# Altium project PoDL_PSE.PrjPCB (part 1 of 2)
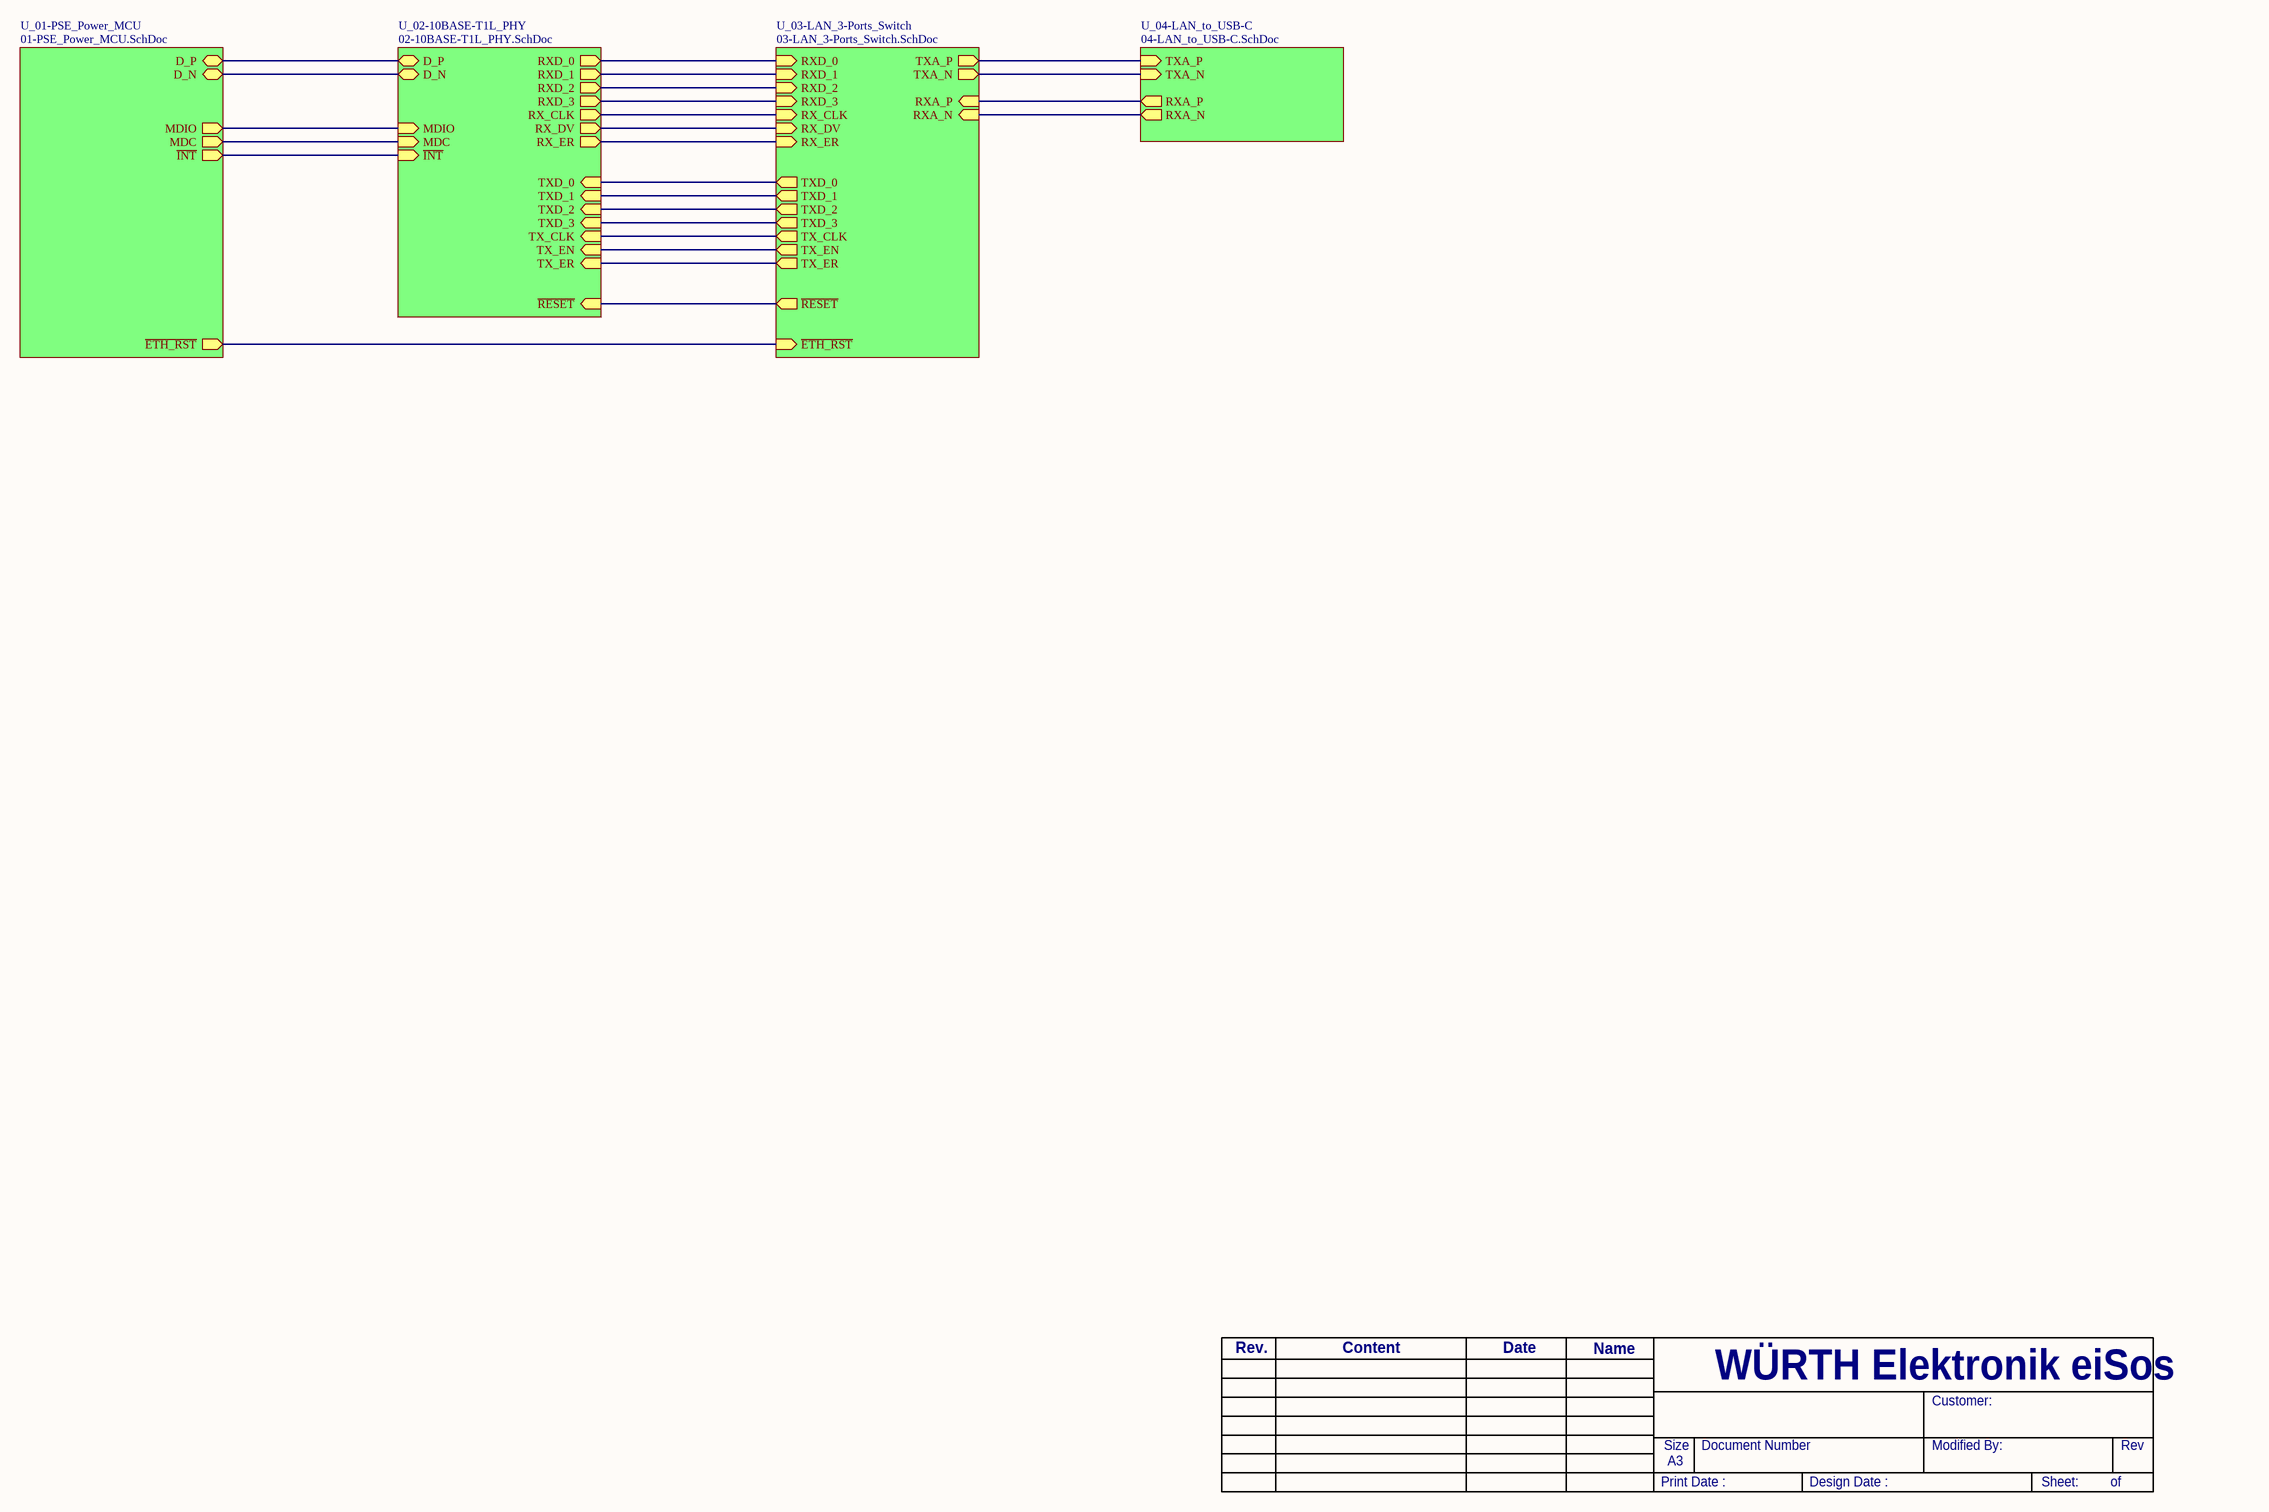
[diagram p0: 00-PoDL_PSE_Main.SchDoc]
5 sheets, 431 parts. Net scope: hierarchical (ports join the sheet entries above them; power ports are global).
Board file: PoDL_PSE_V16.PcbDoc
Sheets:
  00-PoDL_PSE_Main.SchDoc
    U_01-PSE_Power_MCU = 01-PSE_Power_MCU.SchDoc
    U_02-10BASE-T1L_PHY = 02-10BASE-T1L_PHY.SchDoc
    U_03-LAN_3-Ports_Switch = 03-LAN_3-Ports_Switch.SchDoc
    U_04-LAN_to_USB-C = 04-LAN_to_USB-C.SchDoc

## Sheet 00-PoDL_PSE_Main.SchDoc: PSE Main
size A2; Date: Thu 9th Mar, 2023; CompanyName: RGT Supply and Service Ltd.; Engineer: Nattawut; Address1: 285/95 M.3 T.Tonpao Sankampaeng; Address2: Chiangmai 50130 Thailand Tel.+66 89 1645339; Revision: 1.6; SheetNumber: 0; SheetTotal: 4; ContentRev1: Original Document; dateREV1: 09-03-2023; NameRev1: Nattawut; NameRev3: Nattawut; NameRev2: Nattawut; NameRev4: Nattawut; NameRev5: Nattawut; NameRev6: Nattawut; dateREV2: 10-05-2023; dateREV3: 29-10-2023; dateREV4: 13-12-2023; dateREV5: 14-05-2024; dateREV6: 04-07-2024; ContentRev2: Change to AD controller; ContentRev3: Update Power Coupling; ContentRev4: Correct for IC4 unused ports; ContentRev5: Improve for EMC ability; ContentRev6: Add D36, Replace FB7 to R162; Rev1: 1.0; Rev2: 1.1; Rev3: 1.2; Rev4: 1.3; Rev5: 1.4; Rev6: 1.5; Project: PoDL; PageSetup: Record=PageOptions¦CenterHorizontal=True¦CenterVertical=True¦PrintScale=0.73¦XCorrection=1.00¦YCorrection=1.00¦PrintKind=0¦BorderSize=5000000¦LeftOffset=0¦BottomOffset=0¦Orientation=2¦PaperLength=1000¦PaperWidth=1000¦Scale=100¦PaperSource=7¦PrintQuality=-3¦MediaType=1¦DitherType=10¦PrintScaleMode=1¦PaperKind=A3¦PaperIndex=8; dateREV7: 15-09-2024; NameRev7: Nattawut; Rev7: 1.6; ContentRev7: Improve for EMC ability

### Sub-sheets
U_01-PSE_Power_MCU = 01-PSE_Power_MCU.SchDoc: D_P (bidir), D_N (bidir), MDIO (out), ~{ETH_RST} (out), MDC (out), ~{INT} (out)
U_02-10BASE-T1L_PHY = 02-10BASE-T1L_PHY.SchDoc: RXD_0 (out), RXD_1 (out), RXD_2 (out), RXD_3 (out), RX_CLK (out), RX_DV (out), RX_ER (out), TX_ER (in), TX_EN (in), TX_CLK (in), TXD_0 (in), TXD_1 (in), TXD_3 (in), TXD_2 (in), D_P (bidir), D_N (bidir), ~{RESET} (in), MDIO (in), MDC (in), ~{INT} (in)
U_03-LAN_3-Ports_Switch = 03-LAN_3-Ports_Switch.SchDoc: TXA_N (out), TXA_P (out), RXA_N (in), RXA_P (in), ~{RESET} (out), RXD_0 (in), RX_CLK (in), RX_DV (in), RX_ER (in), TX_ER (out), TX_EN (out), TX_CLK (out), TXD_0 (out), TXD_1 (out), RXD_1 (in), RXD_2 (in), RXD_3 (in), TXD_3 (out), TXD_2 (out), ~{ETH_RST} (in)
U_04-LAN_to_USB-C = 04-LAN_to_USB-C.SchDoc: TXA_N (in), TXA_P (in), RXA_N (out), RXA_P (out)

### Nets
D_N: sheet U_01-PSE_Power_MCU/D_N, sheet U_02-10BASE-T1L_PHY/D_N
D_P: sheet U_01-PSE_Power_MCU/D_P, sheet U_02-10BASE-T1L_PHY/D_P
~{ETH_RST}: sheet U_01-PSE_Power_MCU/~{ETH_RST}, sheet U_03-LAN_3-Ports_Switch/~{ETH_RST}
~{INT}: sheet U_01-PSE_Power_MCU/~{INT}, sheet U_02-10BASE-T1L_PHY/~{INT}
MDC: sheet U_01-PSE_Power_MCU/MDC, sheet U_02-10BASE-T1L_PHY/MDC
MDIO: sheet U_01-PSE_Power_MCU/MDIO, sheet U_02-10BASE-T1L_PHY/MDIO
P0_INCLK: sheet U_02-10BASE-T1L_PHY/RX_CLK, sheet U_03-LAN_3-Ports_Switch/RX_CLK
P0_IND0: sheet U_02-10BASE-T1L_PHY/RXD_0, sheet U_03-LAN_3-Ports_Switch/RXD_0
P0_IND1: sheet U_02-10BASE-T1L_PHY/RXD_1, sheet U_03-LAN_3-Ports_Switch/RXD_1
P0_IND2: sheet U_02-10BASE-T1L_PHY/RXD_2, sheet U_03-LAN_3-Ports_Switch/RXD_2
P0_IND3: sheet U_02-10BASE-T1L_PHY/RXD_3, sheet U_03-LAN_3-Ports_Switch/RXD_3
P0_INDV: sheet U_02-10BASE-T1L_PHY/RX_DV, sheet U_03-LAN_3-Ports_Switch/RX_DV
P0_INER: sheet U_02-10BASE-T1L_PHY/RX_ER, sheet U_03-LAN_3-Ports_Switch/RX_ER
P0_OUT/REF_CLK_MODE0: sheet U_02-10BASE-T1L_PHY/TX_CLK, sheet U_03-LAN_3-Ports_Switch/TX_CLK
P0_OUTD0_MODE1: sheet U_02-10BASE-T1L_PHY/TXD_0, sheet U_03-LAN_3-Ports_Switch/TXD_0
P0_OUTD1_MODE2: sheet U_02-10BASE-T1L_PHY/TXD_1, sheet U_03-LAN_3-Ports_Switch/TXD_1
P0_OUTD2_MODE3: sheet U_02-10BASE-T1L_PHY/TXD_2, sheet U_03-LAN_3-Ports_Switch/TXD_2
P0_OUTD3: sheet U_02-10BASE-T1L_PHY/TXD_3, sheet U_03-LAN_3-Ports_Switch/TXD_3
P0_OUTDV: sheet U_02-10BASE-T1L_PHY/TX_EN, sheet U_03-LAN_3-Ports_Switch/TX_EN
P0_OUTER_SPEED: sheet U_02-10BASE-T1L_PHY/TX_ER, sheet U_03-LAN_3-Ports_Switch/TX_ER
~{RESET}: sheet U_02-10BASE-T1L_PHY/~{RESET}, sheet U_03-LAN_3-Ports_Switch/~{RESET}
RXA_N: sheet U_03-LAN_3-Ports_Switch/RXA_N, sheet U_04-LAN_to_USB-C/RXA_N
RXA_P: sheet U_03-LAN_3-Ports_Switch/RXA_P, sheet U_04-LAN_to_USB-C/RXA_P
TXA_N: sheet U_03-LAN_3-Ports_Switch/TXA_N, sheet U_04-LAN_to_USB-C/TXA_N
TXA_P: sheet U_03-LAN_3-Ports_Switch/TXA_P, sheet U_04-LAN_to_USB-C/TXA_P

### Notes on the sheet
- Rev.
- Content
- Date
- Name
- WÜRTH Elektronik eiSos
- Customer:
- Print Date :
- Size
- A3
- Document Number
- Design Date :
- Modified By:
- Sheet:
- of
- Rev

## Sheet 01-PSE_Power_MCU.SchDoc: PSE Port, Power, Controller, MCU
size A2; Date: Thu 9th Mar, 2023; CompanyName: RGT Supply and Service Ltd.; Engineer: Nattawut; Address1: 285/95 M.3 T.Tonpao Sankampaeng; Address2: Chiangmai 50130 Thailand Tel.+66 89 1645339; Revision: 1.6; SheetNumber: 1; SheetTotal: 4; ContentRev1: Original Document; dateREV1: 09-03-2023; NameRev1: Nattawut; NameRev3: Nattawut; NameRev2: Nattawut; NameRev4: Nattawut; NameRev5: Nattawut; NameRev6: Nattawut; dateREV2: 10-05-2023; dateREV3: 29-10-2023; dateREV4: 13-12-2023; dateREV5: 14-05-2024; dateREV6: 04-07-2024; ContentRev2: Change to AD controller; ContentRev3: Update Power Coupling; ContentRev4: Correct for IC4 unused ports; ContentRev5: Improve for EMC ability; ContentRev6: Add D36, Replace FB7 to R162; Rev1: 1.0; Rev2: 1.1; Rev3: 1.2; Rev4: 1.3; Rev5: 1.4; Rev6: 1.5; Project: PoDL; PageSetup: Record=PageOptions¦CenterHorizontal=True¦CenterVertical=True¦PrintScale=0.73¦XCorrection=1.00¦YCorrection=1.00¦PrintKind=0¦BorderSize=5000000¦LeftOffset=0¦BottomOffset=0¦Orientation=2¦PaperLength=1000¦PaperWidth=1000¦Scale=100¦PaperSource=7¦PrintQuality=-3¦MediaType=1¦DitherType=10¦PrintScaleMode=1¦PaperKind=A3¦PaperIndex=8; Rev7: 1.6; ContentRev7: Improve for EMC ability; dateREV7: 15-09-2024; NameRev7: Nattawut
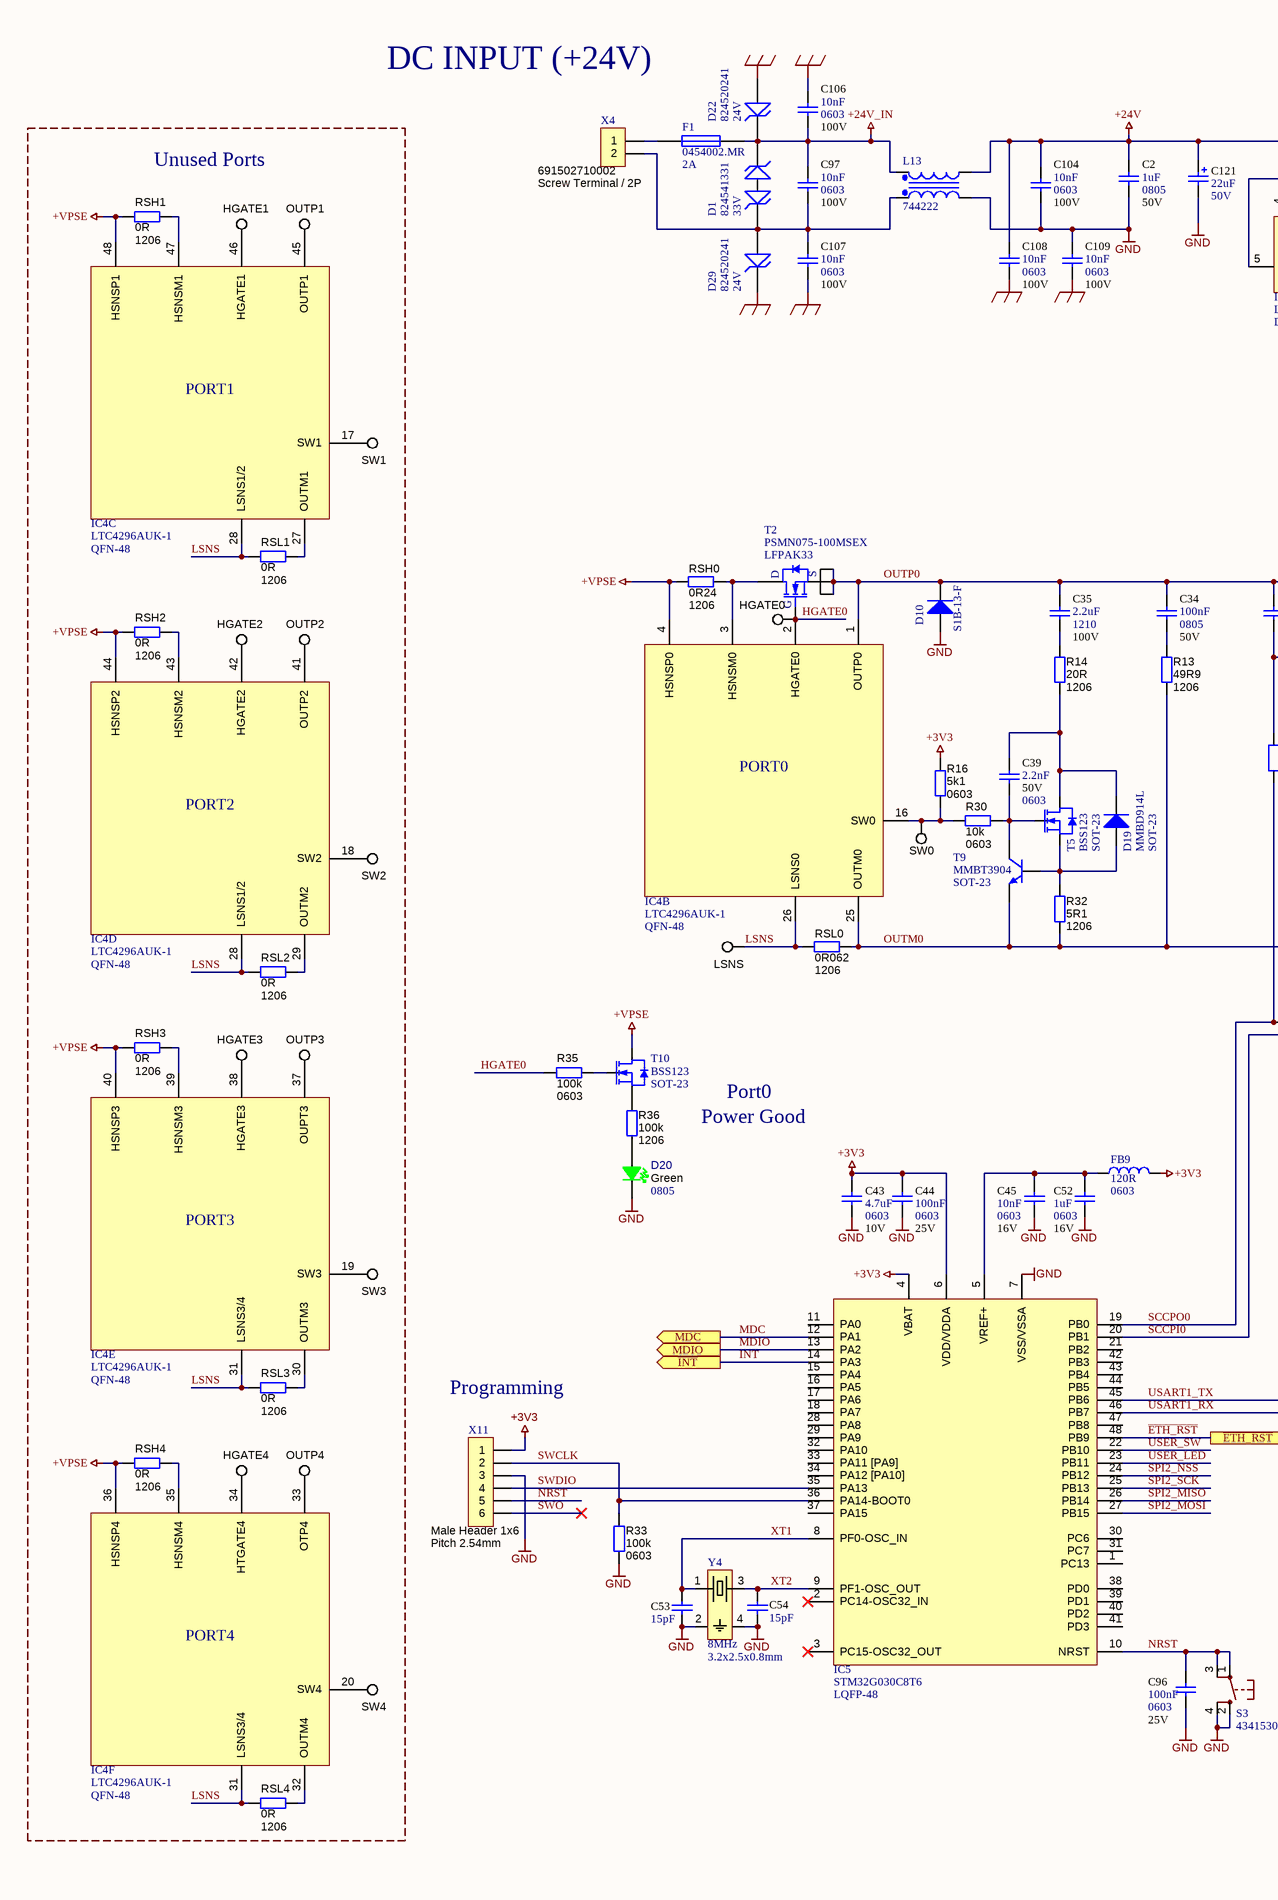
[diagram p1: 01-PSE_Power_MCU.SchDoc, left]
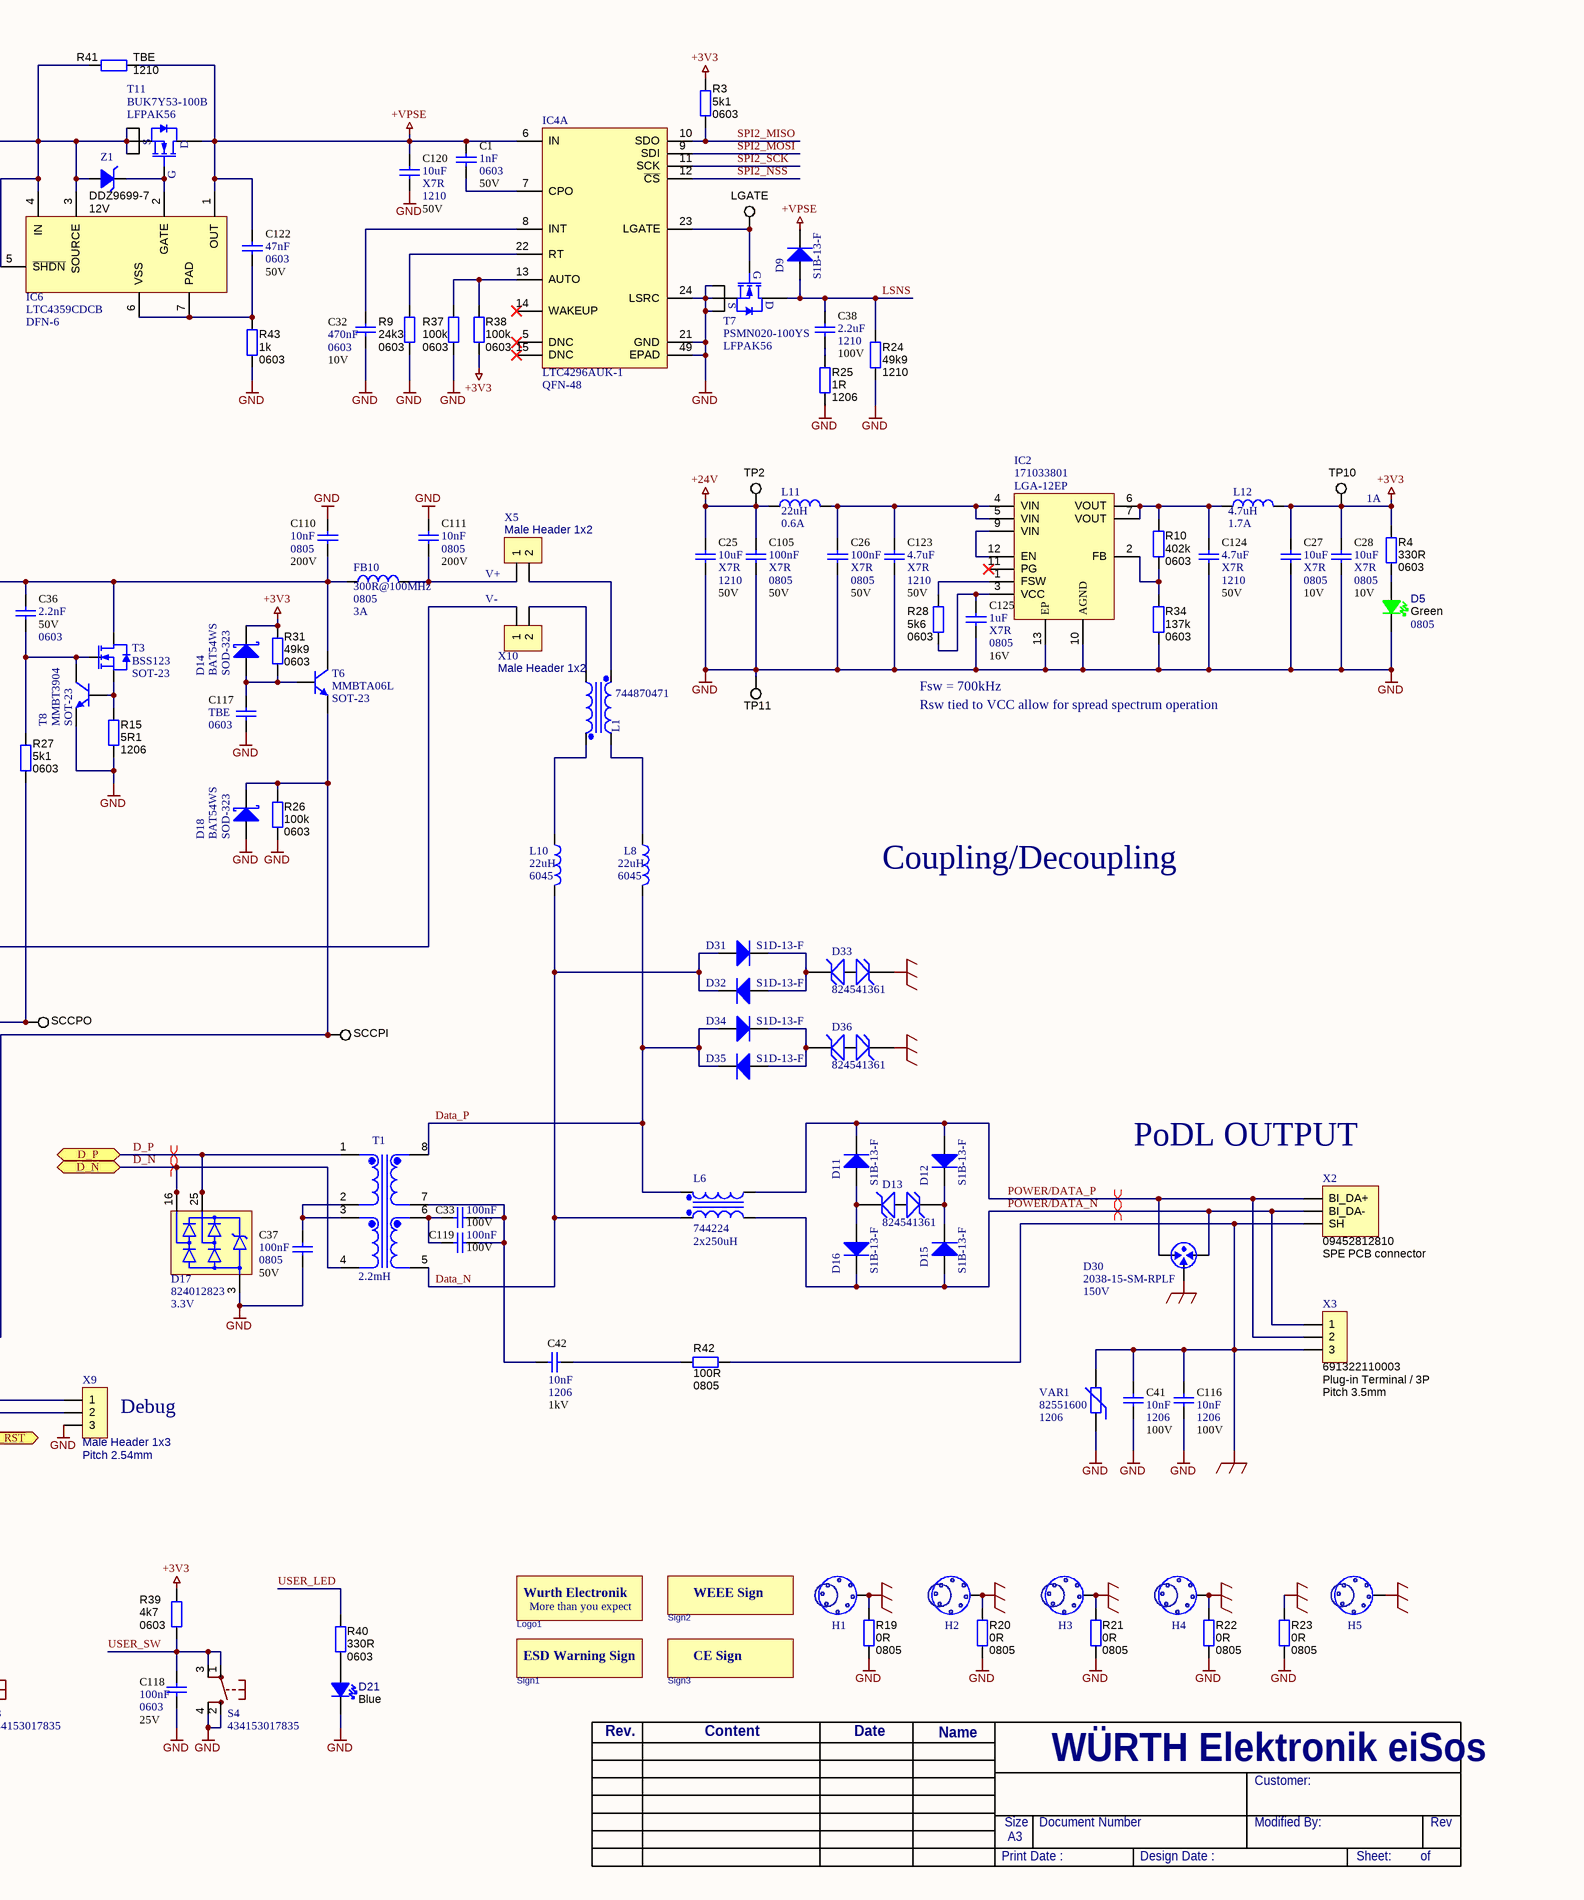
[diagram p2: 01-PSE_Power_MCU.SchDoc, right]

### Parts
C1  value 1nF  VDC_V: 50V  PackageReference: 0603  [CC1608-0603]  (hidden comment: 885012206083)
C2  value 1uF  VDC_V: 50V  PackageReference: 0805  [CC2012-0805]  (hidden comment: 885012207103)
C25  value 10uF  VDC_V: 50V  PackageReference: 1210  Dielectric: X7R  [CC3225-1210]  (hidden comment: 885012209073)
C26  value 100nF  VDC_V: 50V  PackageReference: 0805  Dielectric: X7R  [CC2012-0805]  (hidden comment: 885012207098)
C27  value 10uF  VDC_V: 10V  PackageReference: 0805  Dielectric: X7R  [CC2012-0805]  (hidden comment: 885012207026)
C28  value 10uF  VDC_V: 10V  PackageReference: 0805  Dielectric: X7R  [CC2012-0805]  (hidden comment: 885012207026)
C32  value 470nF  VDC_V: 10V  PackageReference: 0603  [CC1608-0603]  (hidden comment: 885012206024)
C33  value 100nF  VDC_V: 100V  [CC1608-0603]  (hidden comment: 885012206120)
C34  value 100nF  VDC_V: 50V  PackageReference: 0805  [CC2012-0805]  (hidden comment: 885012207098)
C35  value 2.2uF  VDC_V: 100V  PackageReference: 1210  [CC3225-1210]  (hidden comment: 885382209002)
C36  value 2.2nF  VDC_V: 50V  PackageReference: 0603  [CC1608-0603]  (hidden comment: 885012206085)
C37  value 100nF  VDC_V: 50V  PackageReference: 0805  [CC2012-0805]  (hidden comment: 885012207098)
C38  value 2.2uF  VDC_V: 100V  PackageReference: 1210  [CC3225-1210]  (hidden comment: 885382209002)
C39  value 2.2nF  VDC_V: 50V  PackageReference: 0603  [CC1608-0603]  (hidden comment: 885012206085)
C41  value 10nF  PackageReference: 1206  VDC_V: 100V  [CC3216-1206]  (hidden comment: 885012208112)
C42  value 10nF  PackageReference: 1206  VDC_V: 1kV  [CC3216-1206]  (hidden comment: 885342208021)
C43  value 4.7uF  VDC_V: 10V  PackageReference: 0603  [CC1608-0603]  (hidden comment: 885012106012)
C44  value 100nF  VDC_V: 25V  PackageReference: 0603  [CC1608-0603]  (hidden comment: 885012206071)
C45  value 10nF  VDC_V: 16V  PackageReference: 0603  [CC1608-0603]  (hidden comment: 885012206040)
C52  value 1uF  VDC_V: 16V  PackageReference: 0603  [CC1608-0603]  (hidden comment: 885012206052)
C53  value 15pF  [CC1005-0402]  (hidden comment: 885012005056)
C54  value 15pF  [CC1005-0402]  (hidden comment: 885012005056)
C96  value 100nF  VDC_V: 25V  PackageReference: 0603  [CC1608-0603]  (hidden comment: 885012206071)
C97  value 10nF  PackageReference: 0603  VDC_V: 100V  [CC1608-0603]  (hidden comment: 885012206114)
C104  value 10nF  PackageReference: 0603  VDC_V: 100V  [CC1608-0603]  (hidden comment: 885012206114)
C105  value 100nF  VDC_V: 50V  PackageReference: 0805  Dielectric: X7R  [CC2012-0805]  (hidden comment: 885012207098)
C106  value 10nF  PackageReference: 0603  VDC_V: 100V  [CC1608-0603]  (hidden comment: 885012206114)
C107  value 10nF  PackageReference: 0603  VDC_V: 100V  [CC1608-0603]  (hidden comment: 885012206114)
C108  value 10nF  PackageReference: 0603  VDC_V: 100V  [CC1608-0603]  (hidden comment: 885012206114)
C109  value 10nF  PackageReference: 0603  VDC_V: 100V  [CC1608-0603]  (hidden comment: 885012206114)
C110  value 10nF  VDC_V: 200V  PackageReference: 0805  [CC2012-0805]  (hidden comment: 885342207005)
C111  value 10nF  VDC_V: 200V  PackageReference: 0805  [CC2012-0805]  (hidden comment: 885342207005)
C116  value 10nF  PackageReference: 1206  VDC_V: 100V  [CC3216-1206]  (hidden comment: 885012208112)
C117  value TBE  PackageReference: 0603  [CC1608-0603]
C118  value 100nF  VDC_V: 25V  PackageReference: 0603  [CC1608-0603]  (hidden comment: 885012206071)
C119  value 100nF  VDC_V: 100V  [CC1608-0603]  (hidden comment: 885012206120)
C120  value 10uF  VDC_V: 50V  PackageReference: 1210  Dielectric: X7R  [CC3225-1210]  (hidden comment: 885012209073)
C121  value 22uF  VDC_V: 50V  [SMT 6.3mmx5.5mm - WE]  (hidden comment: 865080643008)
C122  value 47nF  VDC_V: 50V  PackageReference: 0603  [CC1608-0603]  (hidden comment: 885012206093)
C123  value 4.7uF  VDC_V: 50V  PackageReference: 1210  Dielectric: X7R  [CC3225-1210]  (hidden comment: 885012209048)
C124  value 4.7uF  VDC_V: 50V  PackageReference: 1210  Dielectric: X7R  [CC3225-1210]  (hidden comment: 885012209048)
C125  value 1uF  VDC_V: 16V  PackageReference: 0805  Dielectric: X7R  [CC2012-0805]  (hidden comment: 885012207051)
D1  Voltage: 33V  [SMC/DO-214AB]  (hidden comment: 824541331)
D5  value Green  PackageReference: 0805  [LED2012 (0805) - Green]  (hidden comment: 150080VS75000)
D9  S1B-13-F  [SMA/DO-214AC]
D10  S1B-13-F  [SMA/DO-214AC]
D11  S1B-13-F  [SMA/DO-214AC]
D12  S1B-13-F  [SMA/DO-214AC]
D13  824541361  [SMC/DO-214AB]
D14  value BAT54WS  [SOD-323]  (hidden comment: BAT54WS-7-F)
D15  S1B-13-F  [SMA/DO-214AC]
D16  S1B-13-F  [SMA/DO-214AC]
D17  Voltage: 3.3V  [DFN1210-6L 1.2X1.0]  (hidden comment: 824012823)
D18  value BAT54WS  [SOD-323]  (hidden comment: BAT54WS-7-F)
D19  value MMBD914L  [SOT-23]  (hidden comment: MMBD914LT1G)
D20  value Green  PackageReference: 0805  [LED2012 (0805) - Green]  (hidden comment: 150080VS75000)
D21  value Blue  [LED1608 (0603) - BLUE]  (hidden comment: 150060BS55040)
D22  Voltage: 24V  [SMB/DO-214AA]  (hidden comment: 824520241)
D29  Voltage: 24V  [SMB/DO-214AA]  (hidden comment: 824520241)
D30  value 150V  [2038-xx]  (hidden comment: 2038-15-SM-RPLF)
D31  S1D-13-F  [SMA/DO-214AC]
D32  S1D-13-F  [SMA/DO-214AC]
D33  824541361  [SMC/DO-214AB]
D34  S1D-13-F  [SMA/DO-214AC]
D35  S1D-13-F  [SMA/DO-214AC]
D36  824541361  [SMC/DO-214AB]
F1  I: 2A  [SET]  (hidden comment: 0454002.MR)
FB9  value 120R  PackageReference: 0603  [CF1608-0603]  (hidden comment: 742792625)
FB10  value 300R@100MHz  PackageReference: 0805  I DC: 3A  [CF2012-0805]  (hidden comment: 742792031)
H1  Hole M3 with Vias  [M3_VIA]  (value not drawn)
H2  Hole M3 with Vias  [M3_VIA]  (value not drawn)
H3  Hole M3 with Vias  [M3_VIA]  (value not drawn)
H4  Hole M3 with Vias  [M3_VIA]  (value not drawn)
H5  Hole M3 with Vias  [M3_VIA]  (value not drawn)
HGATE0  (no value)  [TESTPOINT 1.5mm]
HGATE1  (no value)  [TESTPOINT 1.5mm]
HGATE2  (no value)  [TESTPOINT 1.5mm]
HGATE3  (no value)  [TESTPOINT 1.5mm]
HGATE4  (no value)  [TESTPOINT 1.5mm]
IC2  PackageReference: LGA-12EP  [MAGI³C-VDRM_LGA-12EP]  (hidden comment: 171033801)
IC4  value LTC4296AUK-1  PackageReference: QFN-48  [QFN-48 7x7MM]  (hidden comment: LTC4296AUK-1#PBF)  (parts A,B,C,D,E,F of 6)
IC5  PackageReference: LQFP-48  [QFP-48 7x7MM]  (hidden comment: STM32G030C8T6)
IC6  value LTC4359CDCB  PackageReference: DFN-6  [DFN-6 2X3_0.5]  (hidden comment: LTC4359CDCB#TRMPBF)
L1  PartNumber: 744870471  [Inductor_WE-DD 1280]  (hidden comment: 744870471_(2))
L6  value 2x250uH  [Inductor_WE-SL2]  (hidden comment: 744224)
L8  value 22uH  PackageReference: 6045  [Inductor_WE-LQS 6045]  (hidden comment: 74404064220)
L10  value 22uH  PackageReference: 6045  [Inductor_WE-LQS 6045]  (hidden comment: 74404064220)
L11  value 22uH  I DC: 0.6A  [Inductor_WE-LQS 3015]  (hidden comment: 74404032220)
L12  value 4.7uH  I DC: 1.7A  [Inductor_WE-LQS-4018]  (hidden comment: 74404042047)
L13  744222  [Inductor_WE-SL2]
LGATE  (no value)  [TESTPOINT 1.5mm]
Logo1  Wurth_994x400  [Wurth_994x400]  (value not drawn)  (no BOM)
LSNS  (no value)  [TESTPOINT 1.5mm]
OUTP1  (no value)  [TESTPOINT 1.5mm]
OUTP2  (no value)  [TESTPOINT 1.5mm]
OUTP3  (no value)  [TESTPOINT 1.5mm]
OUTP4  (no value)  [TESTPOINT 1.5mm]
R3  value 5k1  PackageReference: 0603  [CR1608-0603]  (hidden comment: RC0603FR-075K1L)
R4  value 330R  PackageReference: 0603  [CR1608-0603]  (hidden comment: 560112116020)
R9  value 24k3  PackageReference: 0603  [CR1608-0603]  (hidden comment: RC0603FR-0724K3L)
R10  value 402k  PackageReference: 0603  [CR1608-0603]  (hidden comment: RC0603FR-07402KL)
R13  value 49R9  PackageReference: 1206  [CR3216-1206]  (hidden comment: RC1206FR-0749R9L)
R14  value 20R  PackageReference: 1206  [CR3216-1206]  (hidden comment: 560112132008)
R15  value 5R1  PackageReference: 1206  [CR3216-1206]  (hidden comment: RC1206FR-075R1L)
R16  value 5k1  PackageReference: 0603  [CR1608-0603]  (hidden comment: RC0603FR-075K1L)
R19  value 0R  PackageReference: 0805  [CR2012-0805]  (hidden comment: RC0805JR-070RL)
R20  value 0R  PackageReference: 0805  [CR2012-0805]  (hidden comment: RC0805JR-070RL)
R21  value 0R  PackageReference: 0805  [CR2012-0805]  (hidden comment: RC0805JR-070RL)
R22  value 0R  PackageReference: 0805  [CR2012-0805]  (hidden comment: RC0805JR-070RL)
R23  value 0R  PackageReference: 0805  [CR2012-0805]  (hidden comment: RC0805JR-070RL)
R24  value 49k9  PackageReference: 1210  [CR3225-1210]  (hidden comment: RC1210FR-0749K9L)
R25  value 1R  PackageReference: 1206  [CR3216-1206]  (hidden comment: 560112132002)
R26  value 100k  PackageReference: 0603  [CR1608-0603]  (hidden comment: 560112116004)
R27  value 5k1  PackageReference: 0603  [CR1608-0603]  (hidden comment: RC0603FR-075K1L)
R28  value 5k6  PackageReference: 0603  [CR1608-0603]  (hidden comment: 560112116017)
R30  value 10k  PackageReference: 0603  [CR1608-0603]  (hidden comment: 560112116005)
R31  value 49k9  PackageReference: 0603  [CR1608-0603]  (hidden comment: 560112116112)
R32  value 5R1  PackageReference: 1206  [CR3216-1206]  (hidden comment: RC1206FR-075R1L)
R33  value 100k  PackageReference: 0603  [CR1608-0603]  (hidden comment: 560112116004)
R34  value 137k  PackageReference: 0603  [CR1608-0603]  (hidden comment: RC0603FR-07137KL)
R35  value 100k  PackageReference: 0603  [CR1608-0603]  (hidden comment: 560112116004)
R36  value 100k  PackageReference: 1206  [CR3216-1206]  (hidden comment: 560112132034)
R37  value 100k  PackageReference: 0603  [CR1608-0603]  (hidden comment: 560112116004)
R38  value 100k  PackageReference: 0603  [CR1608-0603]  (hidden comment: RC0603FR-07100KL)
R39  value 4k7  PackageReference: 0603  [CR1608-0603]  (hidden comment: 560112116006)
R40  value 330R  PackageReference: 0603  [CR1608-0603]  (hidden comment: 560112116020)
R41  value TBE  PackageReference: 1210  [CR3225-1210]
R42  value 100R  PackageReference: 0805  [CR2012-0805]  (hidden comment: 560112120020)
R43  value 1k  PackageReference: 0603  [CR1608-0603]  (hidden comment: 560112116014)
RSH0  value 0R24  PackageReference: 1206  [CR3216-1206]  (hidden comment: RL1206FR-070R24L)
RSH1  value 0R  PackageReference: 1206  [CR3216-1206]  (hidden comment: CRCW12060000Z0EA)
RSH2  value 0R  PackageReference: 1206  [CR3216-1206]  (hidden comment: CRCW12060000Z0EA)
RSH3  value 0R  PackageReference: 1206  [CR3216-1206]  (hidden comment: CRCW12060000Z0EA)
RSH4  value 0R  PackageReference: 1206  [CR3216-1206]  (hidden comment: CRCW12060000Z0EA)
RSL0  value 0R062  PackageReference: 1206  [CR3216-1206]  (hidden comment: RL1206FR-070R062L)
RSL1  value 0R  PackageReference: 1206  [CR3216-1206]  (hidden comment: CRCW12060000Z0EA)
RSL2  value 0R  PackageReference: 1206  [CR3216-1206]  (hidden comment: CRCW12060000Z0EA)
RSL3  value 0R  PackageReference: 1206  [CR3216-1206]  (hidden comment: CRCW12060000Z0EA)
RSL4  value 0R  PackageReference: 1206  [CR3216-1206]  (hidden comment: CRCW12060000Z0EA)
S3  434153017835  [434153017835]
S4  434153017835  [434153017835]
SCCPI  (no value)  [TESTPOINT 1.5mm]
SCCPO  (no value)  [TESTPOINT 1.5mm]
Sign1  ESD_380x350  [ESD_380x351]  (value not drawn)  (no BOM)
Sign2  WEEE_275x400  [WEEE_275x400]  (value not drawn)  (no BOM)
Sign3  CE_412x295  [CE_412x295]  (value not drawn)  (no BOM)
SW0  (no value)  [TESTPOINT 1.5mm]
SW1  (no value)  [TESTPOINT 1.5mm]
SW2  (no value)  [TESTPOINT 1.5mm]
SW3  (no value)  [TESTPOINT 1.5mm]
SW4  (no value)  [TESTPOINT 1.5mm]
T1  Ind_H: 2.2mH  [749070011_WE-PoDL]  (hidden comment: 749070011)
T2  PackageReference: LFPAK33  [LFPAK33 (SOT1210)]  (hidden comment: PSMN075-100MSEX)
T3  value BSS123  [SOT-23]  (hidden comment: BSS123LT1G)
T5  value BSS123  [SOT-23]  (hidden comment: BSS123LT1G)
T6  value MMBTA06L  [SOT-23]  (hidden comment: MMBTA06LT1G)
T7  value PSMN020-100YS  PackageReference: LFPAK56  [LFPAK56 (SOT669)]  (hidden comment: PSMN020-100YS,115)
T8  value MMBT3904  [SOT-23]  (hidden comment: MMBT3904LT1G)
T9  value MMBT3904  [SOT-23]  (hidden comment: MMBT3904LT1G)
T10  value BSS123  [SOT-23]  (hidden comment: BSS123LT1G)
T11  value BUK7Y53-100B  PackageReference: LFPAK56  [LFPAK56 (SOT669)]  (hidden comment: BUK7Y53-100B,115)
TP2  (no value)  [TESTPOINT 1.5mm]
TP10  (no value)  [TESTPOINT 1.5mm]
TP11  (no value)  [TESTPOINT 1.5mm]
VAR1  PackageReference: 1206  [CV3216-1206]  (hidden comment: 82551600)
X2  value SPE PCB connector  [09452812810]  (hidden comment: 09452812810)
X3  value Plug-in Terminal / 3P  PackageReference: Pitch 3.5mm  [691322110003]  (hidden comment: 691322110003)
X4  value Screw Terminal / 2P  [WE-5027-02P]  (hidden comment: 691502710002)
X5  value Male Header 1x2  [HDR1X2]  (hidden comment: 61300211121)
X9  value Male Header 1x3  PackageReference: Pitch 2.54mm  [HDR1X3]  (hidden comment: 61300311121)
X10  value Male Header 1x2  [HDR1X2]  (hidden comment: 61300211121)
X11  value Male Header 1x6  PackageReference: Pitch 2.54mm  [HDR1X6]  (hidden comment: 61300611121)
Y4  value 8MHz  Package: 3.2x2.5x0.8mm  [CRYSTAL_3225]  (hidden comment: 830108313809)
Z1  value 12V  [SOD-123]  (hidden comment: DDZ9699-7)

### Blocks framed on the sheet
Unused Ports: HGATE1-HGATE4 IC4 OUTP1-OUTP4 RSH1-RSH4 RSL1-RSL4 SW1-SW4

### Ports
D_N (bidir), D_P (bidir), MDC (out), MDIO (out), ~{ETH_RST} (out), ~{INT} (out)

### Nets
+3V3: C27.1 C28.1 C43.1 C44.1 D14.2(K) FB9.2 IC5.4(VBAT) IC5.6(VDD/VDDA) L12.2 R3.1 R4.1 R16.1 R31.1 R38.1 R39.1 TP10.1 X11.1
+24V: C2.1 C25.1 C104.1 C105.1 C108.1 C121.1 IC6.3(SOURCE) IC6.4(IN) IC6.5(~{SHDN}) L11.1 L13.3(L2') R41.2 T11.1(S) T11.2(S) T11.3(S) TP2.1 Z1.2(A)
+24V_IN: C97.1 C106.1 D1.2(K) D22.2(K) F1.2 L13.2(L2)
+VPSE: C1.1 C120.1 C122.1 D9.2(K) IC4.4(HSNSP0) IC4.6(IN) IC4.36(HSNSP4) IC4.40(HSNSP3) IC4.44(HSNSP2) IC4.48(HSNSP1) IC6.1(OUT) R41.1 RSH0.1 RSH1.1 RSH2.1 RSH3.1 RSH4.1 T10.3(D) T11.mb(D)
GND: C2.2 C25.2 C26.2 C27.2 C28.2 C32.2 C37.2 C41.2 C43.2 C44.2 C45.2 C52.2 C53.1 C54.1 C96.2 C104.2 C105.2 C109.1 C110.1 C111.1 C116.2 C117.2 C118.2 C120.2 C121.2 C123.2 C124.2 C125.2 D5.1 D10.1(A) D17.3(GND) D18.1(A) D20.1 D21.1 IC2.10(AGND) IC2.13(EP) IC4.21(GND) IC4.24(LSRC) IC4.49(EPAD) IC5.7(VSS/VSSA) L13.4(L1') R9.2 R15.2 R19.1 R20.1 R21.1 R22.1 R23.1 R24.2 R25.2 R26.1 R33.1 R34.2 R37.1 R43.2 S3.2 S3.4 S4.2 S4.4 T7.1(S) T7.2(S) T7.3(S) T8.2(E) TP11.1 VAR1.1 X9.3 X11.3 Y4.2 Y4.4
SHIELD: C41.1 C106.2 C107.2 C108.2 C109.2 C116.1 D22.1(A) D29.2(K) D30.3 D33.1(A) D36.1(A) H1.0(Hole) H2.0(Hole) H3.0(Hole) H4.0(Hole) H5.0(Hole) R19.2 R20.2 R21.2 R22.2 R23.2 R42.2 VAR1.2 X2.SH X3.3
D_N: D17.1(IO1) D17.6(IO1) T1.4 ; port D_N
D_P: D17.2(IO2) D17.5(IO2) T1.1 ; port D_P
Data_N: D31.1(A) D32.2(K) L6.1(L1) L10.2 T1.5
Data_P: D34.1(A) D35.2(K) L6.2(L2) L8.2 T1.8
~{ETH_RST}: IC5.48(PB9) ; port ~{ETH_RST}
HGATE0: HGATE0.1 IC4.2(HGATE0) R35.2 T2.4(G)
~{INT}: IC5.14(PA3) ; port ~{INT}
LSNS: C38.1 D9.1(A) IC4.26(LSNS0) IC4.28(LSNS1/2) IC4.31(LSNS3/4) LSNS.1 R24.1 RSL0.1 RSL1.1 RSL2.1 RSL3.1 RSL4.1 T7.mb(D)
MDC: IC5.12(PA1) ; port MDC
MDIO: IC5.13(PA2) ; port MDIO
NRST: C96.1 IC5.10(NRST) S3.1 S3.3 X11.5
OUTM0: IC4.25(OUTM0) R13.2 R32.2 RSL0.2 T9.2(E) X10.1
OUTP0: C34.1 C35.1 C36.2 C110.2 D10.2(K) FB10.1 IC4.1(OUTP0) T2.1(S) T2.2(S) T2.3(S) T3.3(D) T6.3(C)
POWER/DATA_N: D15.1(A) D16.2(K) D30.2 L6.4(L1') X2.2(BI_DA-) X3.1
POWER/DATA_P: D11.2(K) D12.1(A) D30.1 L6.3(L2') X2.1(BI_DA+) X3.2
SCCPI0: D18.2(K) IC5.20(PB1) R26.2 SCCPI.1 T6.2(E)
SCCPO0: IC5.19(PB0) R27.2 SCCPO.1
SPI2_MISO: IC4.10(SDO) IC5.26(PB14) R3.2
SPI2_MOSI: IC4.9(SDI) IC5.27(PB15)
SPI2_NSS: IC4.12(~{CS}) IC5.24(PB12)
SPI2_SCK: IC4.11(SCK) IC5.25(PB13)
SWCLK: IC5.36(PA14-BOOT0) R33.2 X11.2
SWDIO: IC5.35(PA13) X11.4
SWO: X11.6
USART1_RX: IC5.46(PB7) X9.2
USART1_TX: IC5.45(PB6) X9.1
USER_LED: IC5.23(PB11) R40.1
USER_SW: C118.1 IC5.22(PB10) R39.2 S4.1 S4.3
XT1: C53.2 IC5.8(PF0-OSC_IN) Y4.1
XT2: C54.2 IC5.9(PF1-OSC_OUT) Y4.3
NetC1_2: C1.2 IC4.7(CPO)
NetC26_1: C26.1 C123.1 IC2.4(VIN) IC2.5(VIN) L11.2
NetC32_1: C32.1 IC4.8(INT)
NetC33_1: C33.1 C119.1 T1.6
NetC33_2: C33.2 C42.1 C119.2 T1.7
NetC34_2: C34.2 R13.1
NetC35_2: C35.2 R14.1
NetC36_1: C36.1 R27.1 T3.1(G) T8.3(C)
NetC37_1: C37.1 T1.2 T1.3
NetC38_2: C38.2 R25.1
NetC39_1: C39.1 R30.2 T5.1(G) T9.3(C)
NetC39_2: C39.2 D19.3(K) R14.2 T5.3(D)
NetC42_2: C42.2 R42.1
NetC45_1: C45.1 C52.1 FB9.1 IC5.5(VREF+)
NetC97_2: C97.2 C107.1 D1.1(A) D29.1(A) L13.1(L1) X4.2
NetC111_2: C111.2 FB10.2 X5.1
NetC117_1: C117.1 D14.1(A) R31.2 T6.1(B)
NetC122_2: C122.2 IC6.6(VSS) IC6.7(PAD) R43.1
NetC124_1: C124.1 IC2.6(VOUT) IC2.7(VOUT) L12.1 R10.2
NetC125_1: C125.1 IC2.3(VCC) R28.2
NetD5_2: D5.2 R4.2
NetD11_1: D11.1(A) D13.2(K) D16.1(A)
NetD12_2: D12.2(K) D13.1(A) D15.2(K)
NetD19_1: D19.1(A) R32.1 T5.2(S) T9.1(B)
NetD20_2: D20.2 R36.1
NetD21_2: D21.2 R40.2
NetD31_2: D31.2(K) D32.1(A) D33.2(K)
NetD34_2: D34.2(K) D35.1(A) D36.2(K)
NetF1_1: F1.1 X4.1
NetHGATE1_1: HGATE1.1 IC4.46(HGATE1)
NetHGATE2_1: HGATE2.1 IC4.42(HGATE2)
NetHGATE3_1: HGATE3.1 IC4.38(HGATE3)
NetHGATE4_1: HGATE4.1 IC4.34(HTGATE4)
NetIC2_1: IC2.1(FSW) R28.1
NetIC2_2: IC2.2(FB) R10.1 R34.1
NetIC2_9: IC2.9(VIN) IC2.12(EN)
NetIC4_3: IC4.3(HSNSM0) RSH0.2 T2.mb(D)
NetIC4_13: IC4.13(AUTO) R37.2 R38.2
NetIC4_16: IC4.16(SW0) R16.2 R30.1 SW0.1
NetIC4_17: IC4.17(SW1) SW1.1
NetIC4_18: IC4.18(SW2) SW2.1
NetIC4_19: IC4.19(SW3) SW3.1
NetIC4_20: IC4.20(SW4) SW4.1
NetIC4_22: IC4.22(RT) R9.1
NetIC4_23: IC4.23(LGATE) LGATE.1 T7.4(G)
NetIC4_27: IC4.27(OUTM1) RSL1.2
NetIC4_29: IC4.29(OUTM2) RSL2.2
NetIC4_30: IC4.30(OUTM3) RSL3.2
NetIC4_32: IC4.32(OUTM4) RSL4.2
NetIC4_33: IC4.33(OTP4) OUTP4.1
NetIC4_35: IC4.35(HSNSM4) RSH4.2
NetIC4_37: IC4.37(OUPT3) OUTP3.1
NetIC4_39: IC4.39(HSNSM3) RSH3.2
NetIC4_41: IC4.41(OUTP2) OUTP2.1
NetIC4_43: IC4.43(HSNSM2) RSH2.2
NetIC4_45: IC4.45(OUTP1) OUTP1.1
NetIC4_47: IC4.47(HSNSM1) RSH1.2
NetIC6_2: IC6.2(GATE) T11.4(G) Z1.1(K)
NetL1_1: L1.1(L1) X5.2
NetL1_2: L1.2(L2) L10.1
NetL1_3: L1.3(L1') L8.1
NetL1_4: L1.4(L2') X10.2
NetR15_1: R15.1 T3.2(S) T8.1(B)
NetR35_1: R35.1 T10.1(G)
NetR36_2: R36.2 T10.2(S)

Not connected (* = marked no-connect by the designer): IC2 11(PG)*; IC4 5(DNC)* 14(WAKEUP)* 15(DNC)*; IC5 1(PC13) 2(PC14-OSC32_IN)* 3(PC15-OSC32_OUT)* 11(PA0) 15(PA4) 16(PA5) 17(PA6) 18(PA7) 21(PB2) 28(PA8) 29(PA9) 30(PC6) 31(PC7) 32(PA10) 33(PA11_[PA9]) 34(PA12_[PA10]) 37(PA15) 38(PD0) 39(PD1) 40(PD2) 41(PD3) 42(PB3) 43(PB4) 44(PB5) 47(PB8)

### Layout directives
differential pair: D_N, D_P, POWER/DATA_N, POWER/DATA_P

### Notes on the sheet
- DC INPUT (+24V)
- 1A
- (near X5) V+
- V-
- Fsw = 700kHz
- Rsw tied to VCC allow for spread spectrum operation
- Coupling/Decoupling
- Port0
- Power Good
- (near X2) PoDL OUTPUT
- Programming
- (near X9) Debug
- Rev.
- Content
- Date
- Name
- WÜRTH Elektronik eiSos
- Customer:
- Print Date :
- Size
- A3
- Document Number
- Design Date :
- Modified By:
- Sheet:
- of
- Rev

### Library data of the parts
C1 = 885012206083: CAP, CERM, 1nF, 50V, +/-10%, X7R, 0603; Manufacturer: Wurth; Polarized: N; TaMax_C: 125; TaMin_C: -55; Tolerance_%: 10%; CompType: Capacitor
C2 = 885012207103: CAP, CERM, 1uF, 50V, +/-10%, X7R, 0805; Manufacturer: Wurth; Polarized: N; TaMax_C: 125; TaMin_C: -55; Tolerance_%: 10; CompType: Capacitor
C25 C120 = 885012209073: CAP, CERM, 10uF, 50V, +/-10%, X7R, 1210; Manufacturer: Wurth; Polarized: N; TaMax_C: 125; TaMin_C: -55; Tolerance_%: 10%; CompType: Capacitor
C26 C34 C37 C105 = 885012207098: CAP, CERM, 100nF, 50V, +/-10%, X7R, 0805; Manufacturer: Wurth; Polarized: N; TaMax_C: 125; TaMin_C: -55; Tolerance_%: 10; CompType: Capacitor
C27 C28 = 885012207026: CAP, CERM, 10uF, 10V, +/-10%, X7R, 0805; Manufacturer: Wurth; Polarized: N; TaMax_C: 125; TaMin_C: -55; Tolerance_%: 10; CompType: Capacitor
C32 = 885012206024: CAP, CERM, 470nF, 10V, +/-10%, X7R, 0603; Manufacturer: Wurth; Polarized: N; TaMax_C: 125; TaMin_C: -55; Tolerance_%: 10; CompType: Capacitor
C33 C119 = 885012206120: CAP, CERM, 100nF, 100V, +/-10%, X7R, 0603; Manufacturer: Wurth; Polarized: N; TaMax_C: 125; TaMin_C: -55; Tolerance_%: 10; CompType: Capacitor
C35 C38 = 885382209002: CAP, CERM, 2.2uF, 100V, +/-10%, X7R, 1210; Manufacturer: Wurth; Polarized: N; TaMax_C: 125; TaMin_C: -55; Tolerance_%: 10%; CompType: Capacitor
C36 C39 = 885012206085: CAP, CERM, 2.2nF, 50V, +/-10%, X7R, 0603; Manufacturer: Wurth; Polarized: N; TaMax_C: 125; TaMin_C: -55; Tolerance_%: 10%; CompType: Capacitor
C41 C116 = 885012208112: CAP, CERM, 10nF, 100V, +/-10%, X7R, 1206; Manufacturer: Wurth; Polarized: N; TaMax_C: 125; TaMin_C: -55; Tolerance_%: 10; CompType: Capacitor
C42 = 885342208021: CAP, CERM, 10nF, 1kV, +/-10%, X7R, 1206; Manufacturer: Wurth; Polarized: N; TaMax_C: 125; TaMin_C: -55; Tolerance_%: 10; CompType: Capacitor
C43 = 885012106012: CAP, CERM, 4.7uF, 10V, +/-20%, X5R, 0603; Manufacturer: Wurth; Polarized: N; TaMax_C: 85; TaMin_C: -55; Tolerance_%: 20%; CompType: Capacitor
C44 C96 C118 = 885012206071: CAP, CERM, 100nF, 25V, +/-10%, X7R, 0603; Manufacturer: Wurth; Polarized: N; TaMax_C: 125; TaMin_C: -55; Tolerance_%: 10; CompType: Capacitor
C45 = 885012206040: CAP, CERM, 10nF, 16V, +/-10%, X7R, 0603; Manufacturer: Wurth; Polarized: N; TaMax_C: 125; TaMin_C: -55; Tolerance_%: 10; CompType: Capacitor
C52 = 885012206052: CAP, CERM, 1uF, 16V, +/-10%, X7R, 0603; Manufacturer: Wurth; Polarized: N; TaMax_C: 125; TaMin_C: -55; Tolerance_%: 10%; CompType: Capacitor
C53 C54 = 885012005056: CAP, CERM, 15pF, 50V, +/-5%, C0G, 0402; Manufacturer: Wurth; Polarized: N; TaMax_C: 125; TaMin_C: -55; Tolerance_%: 5; CompType: Capacitor
C97 C104 C106-C109 = 885012206114: CAP, CERM, 10nF, 100V, +/-10%, X7R, 0603; Manufacturer: Wurth; Polarized: N; TaMax_C: 125; TaMin_C: -55; Tolerance_%: 10%; CompType: Capacitor
C110 C111 = 885342207005: CAP, CERM, 10nF, 200V, +/-10%, X7R, 0805; Manufacturer: Wurth; Polarized: N; TaMax_C: 125; TaMin_C: -55; Tolerance_%: 10; CompType: Capacitor
C117 = TBE_CAP_0603: CAP, CERM, TBE, 0603; Polarized: N; TaMax_C: 125; TaMin_C: -55; CompType: Capacitor
C121 = 865080643008: CAP, ECAP, 22uF, 50V, +/-20%, 6.3mm x 5.5mm; Manufacturer: Wurth; ESR_Ohm: 1.3Ohm; IRMS_A: 0.150A; Polarized: Y; TaMax_C: 105; TaMin_C: -55; Tolerance_%: 20; CompType: Capacitor
C122 = 885012206093: CAP, CERM, 47nF, 50V, +/-10%, X7R, 0603; Manufacturer: Wurth; Polarized: N; TaMax_C: 125; TaMin_C: -55; Tolerance_%: 10%; CompType: Capacitor
C123 C124 = 885012209048: CAP, CERM, 4.7uF, 50V, +/-10%, X7R, 1210; Manufacturer: Wurth; Polarized: N; TaMax_C: 125; TaMin_C: -55; Tolerance_%: 10%; CompType: Capacitor
C125 = 885012207051: CAP, CERM, 1uF, 16V, +/-10%, X7R, 0805; Manufacturer: Wurth; Polarized: N; TaMax_C: 125; TaMin_C: -55; Tolerance_%: 10; CompType: Capacitor
D1 = 824541331: DIODE, TVS , 33V, 1.5kW, Bidirection, SMC; Manufacturer: Wurth; Power: 1500W
D5 D20 = 150080VS75000: LED 570NM GREEN 0805 SMD; Manufacturer: Wurth
D9-D12 D15 D16 = S1B-13-F: DIODE, Rectifiers, 100V, 1A, SMA; Manufacturer: Diodes
D13 D33 D36 = 824541361: DIODE, TVS , 36V, 1.5kW, Bidirection, SMC; Manufacturer: Wurth; Power: 1500W
D14 D18 = BAT54WS-7-F: DIODE, Schottky, 30V, 0.1A, SOD-323; Manufacturer: Diodes Inc
D17 = 824012823: DIODE, TVS Super Speed , 3.3V, DFN1210-6L; Manufacturer: Wurth
D19 = MMBD914LT1G: DIODE, Switching, 100V, 0.2A, SOT-23; Manufacturer: Onsemi
D21 = 150060BS55040: LED 470NM BLUE 0603 SMD; Manufacturer: Wurth
D22 D29 = 824520241: DIODE, TVS , 24V, 600W, Unidirection, SMB; Manufacturer: Wurth
D30 = 2038-15-SM-RPLF: Gas Discharge Tubes, 150V, 1pF, 5x7.5mm, SMD; Manufacturer: Bourns
D31 D32 D34 D35 = S1D-13-F: DIODE, Rectifiers, 200V, 1A, SMA; Manufacturer: Diodes
F1 = 0454002.MR: FUSE, SMT, 2.0A, 125V, Slow Blow, 6.1x 2.69mm; Manufacturer: Littelfuse
FB9 = 742792625: Ferrite Bead 120R @ 100MHz / 0603 / 2.0A; Manufacturer: Wurth
FB10 = 742792031: Ferrite Bead 300R @ 100MHz / 0805 / 3.0A; Manufacturer: Wurth
H1-H5 = Hole M3 with Vias: SAP: xxxx
HGATE0-HGATE4 LGATE LSNS OUTP1-OUTP4 SCCPI SCCPO SW0-SW4 TP2 TP10 TP11 = TP / 1.5mm: Test Point, SMT, Miniature; Value: 1.5mm
IC2 = 171033801: IC REG BUCK, ADJ, 3A, LGA-16EP; Manufacturer: Wurth
IC4 = LTC4296AUK-1#PBF: IC SPoE PSE, 5-Ports, 10Base-T1L, 6-60V, QFN-48; Manufacturer: Analog Devices
IC5 = STM32G030C8T6: IC MCU, STM32G030C8T6, 32bit, 64kB, 64MHz,  LQFP-48; Manufacturer: ST
IC6 = LTC4359CDCB#TRMPBF: IC PMIC, Ideal Diode, 4-80V, DFN-6; Manufacturer: Analog Devices
L1 = 744870471_(2): Coupled Inductor 2x470uH / 12.5x12.5mm /0.7A; Manufacturer: Wurth; Rdc: 2x1.0; I DC: 0.7A
L6 = 744224: Common Mode Chokes 2x250uH / 9.2x6mm / 1200mA; Manufacturer: Wurth; Rdc: 0.13; I DC: 1.2A
L8 L10 = 74404064220: Inductor 22uH / 6045 / 2.1A; Manufacturer: Wurth
L11 = 74404032220: Inductor 22uH / 3015 / 0.6A; Manufacturer: Wurth
L12 = 74404042047: Inductor 4.7uH / 4018 / 1.7A; Manufacturer: Wurth
L13 = 744222: Common Mode Chokes 2x1000uH / 9.2x6mm / 800mA; Manufacturer: Wurth; Rdc: 0.207; I DC: 0.8A
R3 R16 R27 = RC0603FR-075K1L: RES, 5.1kohm, 1%, 0.1W, 0603; Manufacturer: Yageo; CompType: Resistor; Power_W: 0.1
R4 R40 = 560112116020: RES, 330 ohm, 1%, 0.1W, 0603; Manufacturer: Wurth; CompType: Resistor; Power_W: 0.1
R9 = RC0603FR-0724K3L: RES, 24.3kohm, 1%, 0.1W, 0603; Manufacturer: Yageo; CompType: Resistor; Power_W: 0.1
R10 = RC0603FR-07402KL: RES, 402kohm, 1%, 0.1W, 0603; Manufacturer: Yageo; CompType: Resistor; Power_W: 0.1
R13 = RC1206FR-0749R9L: RES, 49.9 ohm, 1%, 0.25W, 1206; Manufacturer: Yageo; CompType: Resistor; Power_W: 0.25
R14 = 560112132008: RES, 20 ohm, 1%, 0.25W, 1206; Manufacturer: Wurth; CompType: Resistor; Power_W: 0.25
R15 R32 = RC1206FR-075R1L: RES, 5.1 ohm, 1%, 0.25W, 1206; Manufacturer: Yageo; CompType: Resistor; Power_W: 0.25
R19-R23 = RC0805JR-070RL: RES, 0 ohm, -%, 0.125W, 0805; Manufacturer: Yageo; CompType: Resistor; Power_W: 0.125
R24 = RC1210FR-0749K9L: RES, 49.9kohm, 1%, 0.5W, 1210; Manufacturer: YAGEO; CompType: Resistor
R25 = 560112132002: RES, 1 ohm, 1%, 0.25W, 1206; Manufacturer: Wurth; CompType: Resistor
R26 R33 R35 R37 = 560112116004: RES, 100kohm, 1%, 0.1W, 0603; Manufacturer: Wurth; CompType: Resistor; Power_W: 0.1
R28 = 560112116017: RES, 5.6kohm, 1%, 0.1W, 0603; Manufacturer: Wurth; CompType: Resistor; Power_W: 0.1
R30 = 560112116005: RES, 10kohm, 1%, 0.1W, 0603; Manufacturer: Wurth; CompType: Resistor; Power_W: 0.1
R31 = 560112116112: RES, 49.9kohm, 1%, 0.1W, 0603; Manufacturer: Wurth; CompType: Resistor; Power_W: 0.1
R34 = RC0603FR-07137KL: RES, 137kohm, 1%, 0.1W, 0603; Manufacturer: Yageo; CompType: Resistor; Power_W: 0.1
R36 = 560112132034: RES, 100kohm, 1%, 0.25W, 1206; Manufacturer: Wurth; CompType: Resistor; Power_W: 0.25
R38 = RC0603FR-07100KL: RES, 100kohm, 1%, 0.1W, 0603; Manufacturer: Yageo; CompType: Resistor; Power_W: 0.1
R39 = 560112116006: RES, 4.7kohm, 1%, 0.1W, 0603; Manufacturer: Wurth; CompType: Resistor; Power_W: 0.1
R41 = TBE_RES_1210: RES, TBE, 1%, 0.5W, 1210; CompType: Resistor
R42 = 560112120020: RES, 100 ohm, 1%, 0.125W, 0805; Manufacturer: Wurth; CompType: Resistor; Power_W: 0.125
R43 = 560112116014: RES, 1kohm, 1%, 0.1W, 0603; Manufacturer: Wurth; CompType: Resistor; Power_W: 0.1
RSH0 = RL1206FR-070R24L: RES, 0.24 ohm, 1%, 0.25W, 1206; Manufacturer: YAGEO; CompType: Resistor; Power_W: 1
RSH1-RSH4 RSL1-RSL4 = CRCW12060000Z0EA: RES, 0 ohm, -%, 0.25W, 1206; Manufacturer: Vishay; CompType: Resistor; Power_W: 0.25
RSL0 = RL1206FR-070R062L: RES, 0.062 ohm, 1%, 0.25W, 1206; Manufacturer: YAGEO; CompType: Resistor; Power_W: 1
S3 S4 = 434153017835: SWITCH TACTILE, SPST-NO, 350gf, 0.05A, 12V; Manufacturer: Wurth
T1 = 749070011: Trans, PoDL, 2.2mH, SMT; Manufacturer: Wurth; CompType: Transformer; Ns1toNp: 1:1
T2 = PSMN075-100MSEX: MOSFET, N-CH, 100V, 18A, LFPAK33; Manufacturer: Nexperia
T3 T5 T10 = BSS123LT1G: MOSFET, N-CH, 100V, 0.17A, SOT-23; Manufacturer: Onsemi
T6 = MMBTA06LT1G: Transistor, NPN, 80V, 0.5A, SOT-23; Manufacturer: ON Semi
T7 = PSMN020-100YS,115: MOSFET, N-CH, 100V, 43A, LFPAK56; Manufacturer: Nexperia
T8 T9 = MMBT3904LT1G: Transistor, NPN, 40V, 0.2A, SOT-23; Manufacturer: ON Semi
T11 = BUK7Y53-100B,115: MOSFET, N-CH, 100V, 24.8A, LFPAK56; Manufacturer: Nexperia
VAR1 = 82551600: Varistor, 85Vdc, 60Vac, 160pF, 1206; Manufacturer: Wurth
X2 = 09452812810: CON, SPE, 2P, Shield, 4A, R/A, INS; Manufacturer: HARTING; CompType: Connector
X3 = 691322110003: CON, Terminal Block, Plug-in, 3P, P3.5mm, 10A, R/A, INS; Manufacturer: Wurth; CompType: Connector
X4 = 691502710002: CON, Terminal Block, Screw, 2P, P5.0mm, 15A, INS; Manufacturer: Wurth; CompType: Connector
X5 X10 = 61300211121: CON, Header, Male, 2P, P2.54mm, Straight, INS; Manufacturer: Wurth; CompType: Connector
X9 = 61300311121: CON, Header, Male, 3P, P2.54mm, Straight, INS; Manufacturer: Wurth; CompType: Connector
X11 = 61300611121: CON, Header, Male, 6P, P2.54mm, Straight, INS; Manufacturer: Wurth; CompType: Connector
Y4 = 830108313809: Crystal / 8MHz / 12pF / 30ppm; Manufacturer: Wurth
Z1 = DDZ9699-7: DIODE, ZENER, 12V, 500MW, SOD-123; Manufacturer: Diodes Inc

## Sheet 02-10BASE-T1L_PHY.SchDoc: ADIN1100 10BASE-T1L PHY
size A2; Date: Thu 9th Mar, 2023; CompanyName: RGT Supply and Service Ltd.; Engineer: Nattawut; Address1: 285/95 M.3 T.Tonpao Sankampaeng; Address2: Chiangmai 50130 Thailand Tel.+66 89 1645339; Revision: 1.6; SheetNumber: 2; SheetTotal: 4; ContentRev1: Original Document; dateREV1: 09-03-2023; NameRev1: Nattawut; NameRev3: Nattawut; NameRev2: Nattawut; NameRev4: Nattawut; NameRev5: Nattawut; NameRev6: Nattawut; dateREV2: 10-05-2023; dateREV3: 29-10-2023; dateREV4: 13-12-2023; dateREV5: 14-05-2024; dateREV6: 04-07-2024; ContentRev2: Change to AD controller; ContentRev3: Update Power Coupling; ContentRev4: Correct for IC4 unused ports; ContentRev5: Improve for EMC ability; ContentRev6: Add D36, Replace FB7 to R162; Rev1: 1.0; Rev2: 1.1; Rev3: 1.2; Rev4: 1.3; Rev5: 1.4; Rev6: 1.5; Project: PoDL; PageSetup: Record=PageOptions¦CenterHorizontal=True¦CenterVertical=True¦PrintScale=0.73¦XCorrection=1.00¦YCorrection=1.00¦PrintKind=0¦BorderSize=5000000¦LeftOffset=0¦BottomOffset=0¦Orientation=2¦PaperLength=1000¦PaperWidth=1000¦Scale=100¦PaperSource=7¦PrintQuality=-3¦MediaType=1¦DitherType=10¦PrintScaleMode=1¦PaperKind=A3¦PaperIndex=8; Rev7: 1.6; ContentRev7: Improve for EMC ability; dateREV7: 15-09-2024; NameRev7: Nattawut
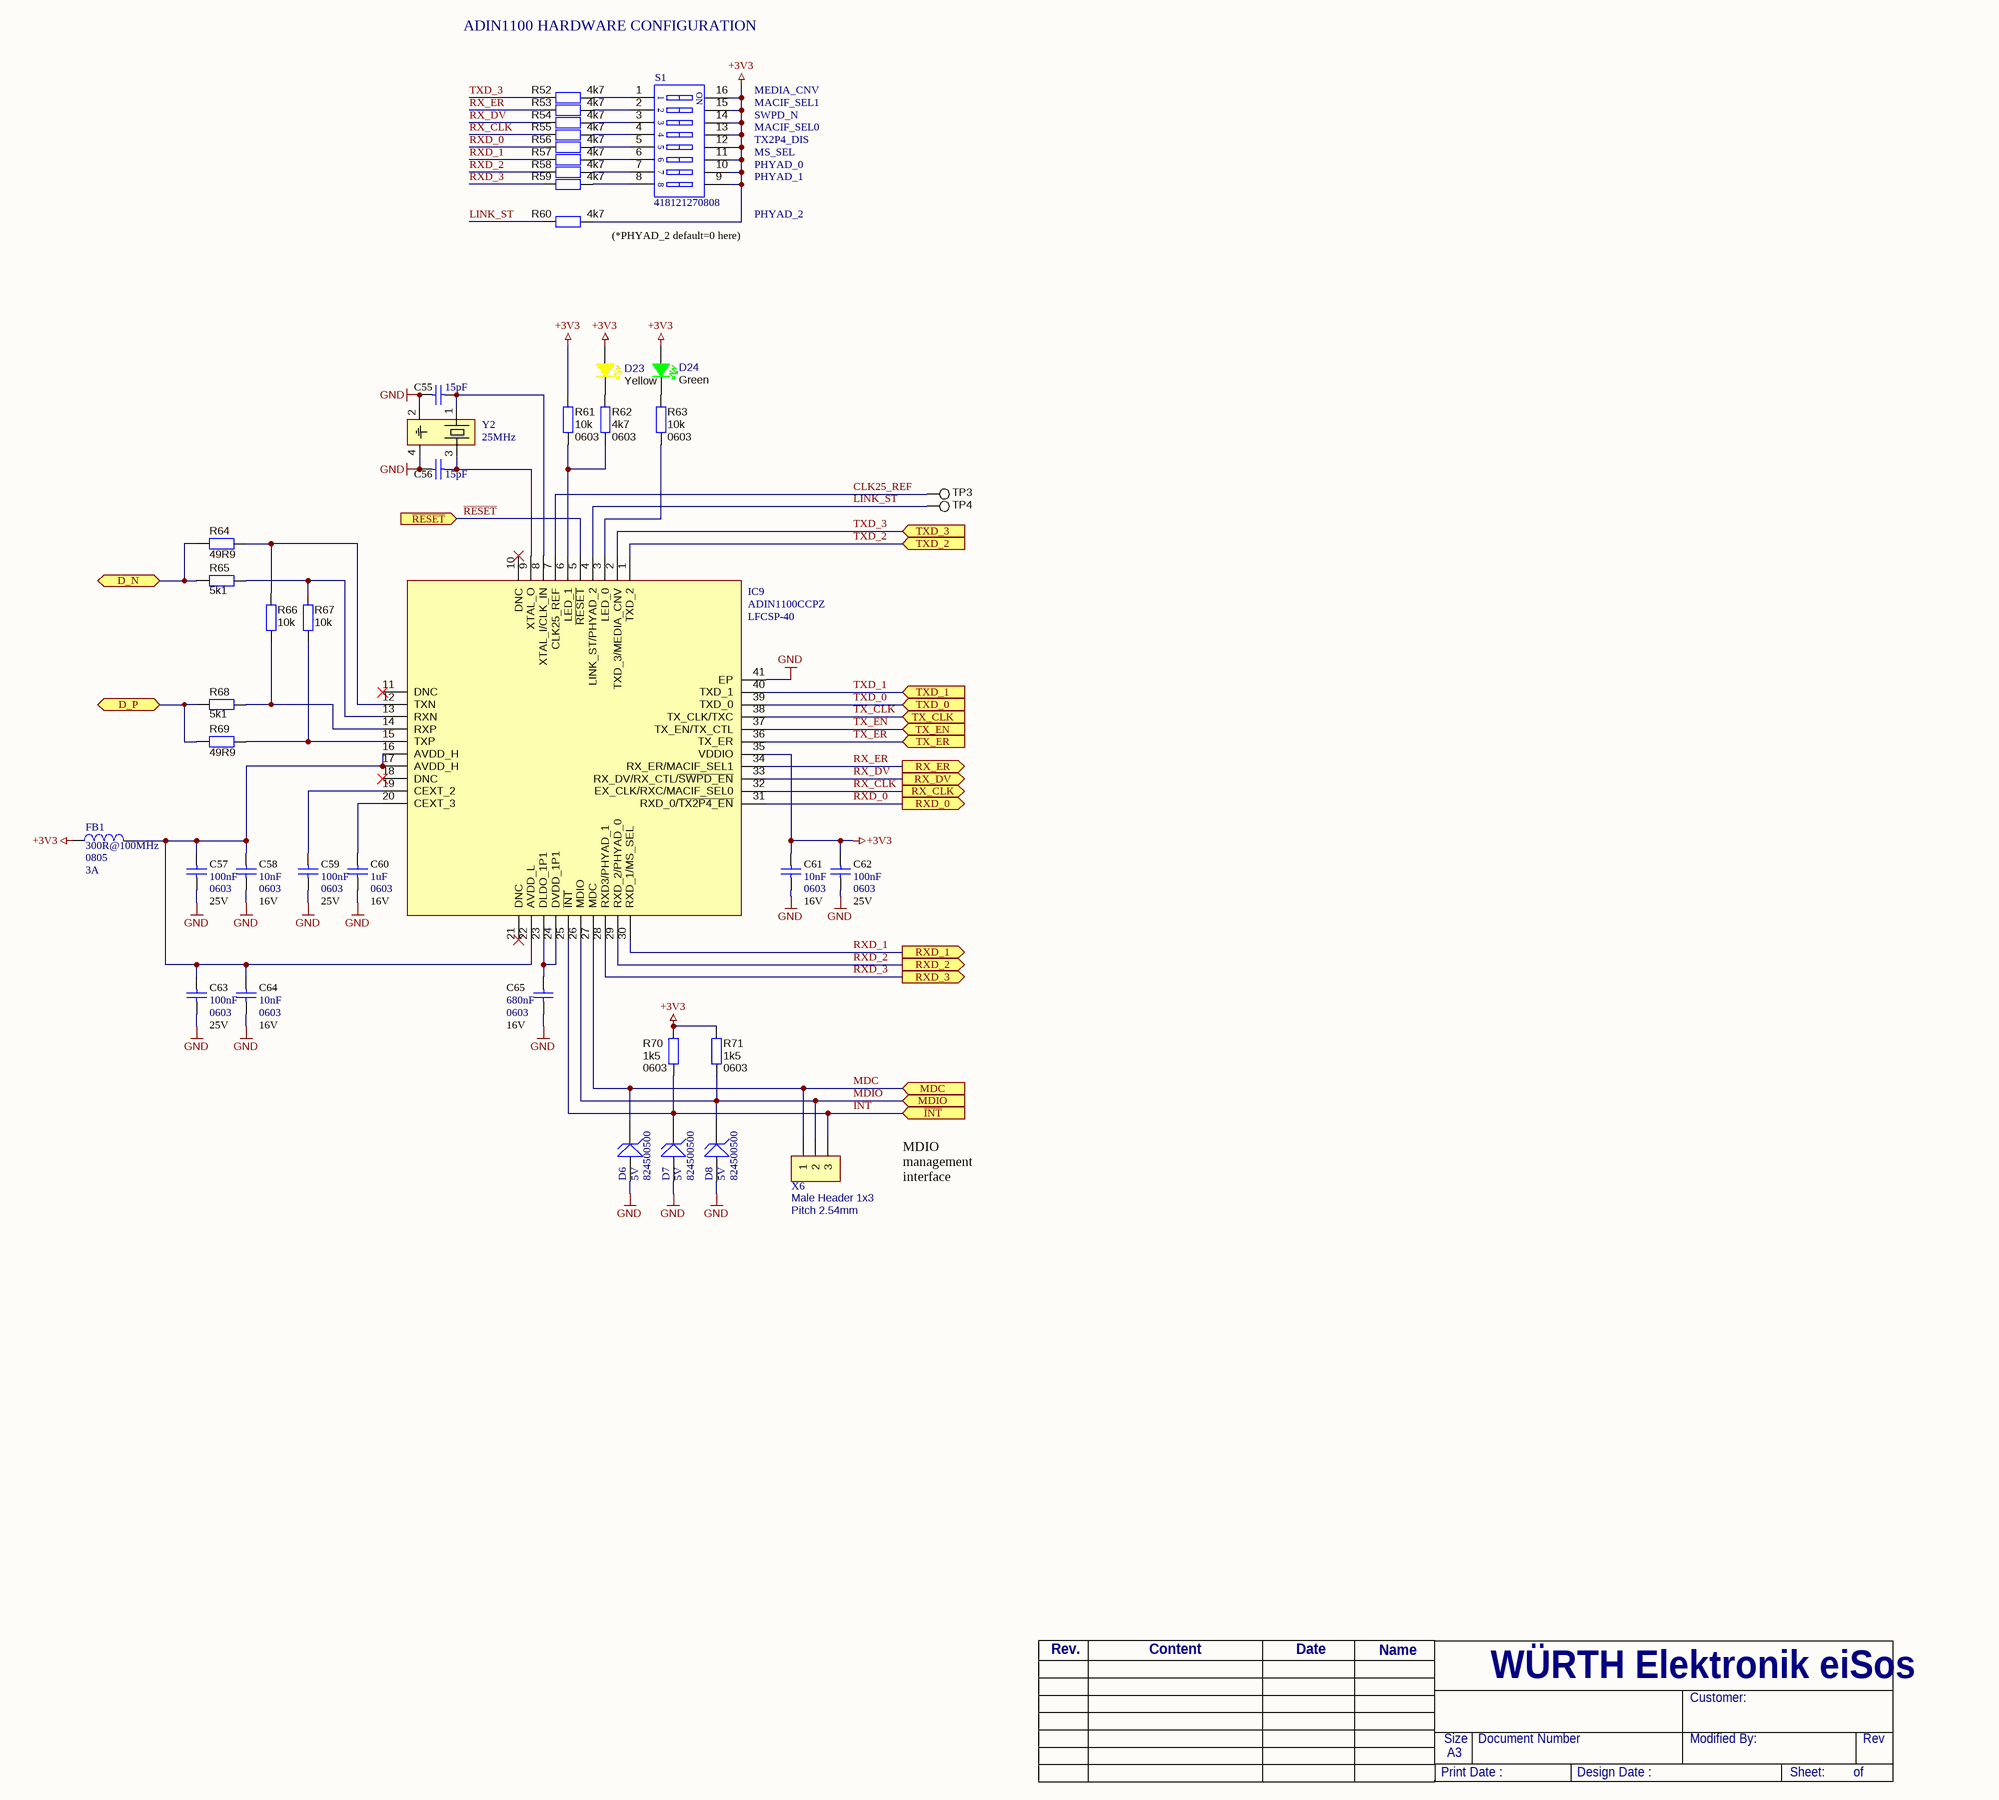
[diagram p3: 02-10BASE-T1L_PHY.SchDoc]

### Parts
C55  value 15pF  [CC1005-0402]  (hidden comment: 885012005056)
C56  value 15pF  [CC1005-0402]  (hidden comment: 885012005056)
C57  value 100nF  VDC_V: 25V  PackageReference: 0603  [CC1608-0603]  (hidden comment: 885012206071)
C58  value 10nF  VDC_V: 16V  PackageReference: 0603  [CC1608-0603]  (hidden comment: 885012206040)
C59  value 100nF  VDC_V: 25V  PackageReference: 0603  [CC1608-0603]  (hidden comment: 885012206071)
C60  value 1uF  VDC_V: 16V  PackageReference: 0603  [CC1608-0603]  (hidden comment: 885012206052)
C61  value 10nF  VDC_V: 16V  PackageReference: 0603  [CC1608-0603]  (hidden comment: 885012206040)
C62  value 100nF  VDC_V: 25V  PackageReference: 0603  [CC1608-0603]  (hidden comment: 885012206071)
C63  value 100nF  VDC_V: 25V  PackageReference: 0603  [CC1608-0603]  (hidden comment: 885012206071)
C64  value 10nF  VDC_V: 16V  PackageReference: 0603  [CC1608-0603]  (hidden comment: 885012206040)
C65  value 680nF  VDC_V: 16V  PackageReference: 0603  [CC1608-0603]  (hidden comment: 885012206051)
D6  Voltage: 5V  [SMA/DO-214AC]  (hidden comment: 824500500)
D7  Voltage: 5V  [SMA/DO-214AC]  (hidden comment: 824500500)
D8  Voltage: 5V  [SMA/DO-214AC]  (hidden comment: 824500500)
D23  value Yellow  [LED1608 (0603) - YELLOW]  (hidden comment: LTST-C190KSKT)
D24  value Green  [LED1608 (0603) - Green]  (hidden comment: 150060VS75020)
FB1  value 300R@100MHz  PackageReference: 0805  I DC: 3A  [CF2012-0805]  (hidden comment: 742792031)
IC9  value ADIN1100CCPZ  PackageReference: LFCSP-40  [QFN-40 6x6MM]  (hidden comment: ADIN1100CCPZ-R7)
R52  value 4k7  [CR1608-0603]  (hidden comment: 560112116006)
R53  value 4k7  [CR1608-0603]  (hidden comment: 560112116006)
R54  value 4k7  [CR1608-0603]  (hidden comment: 560112116006)
R55  value 4k7  [CR1608-0603]  (hidden comment: 560112116006)
R56  value 4k7  [CR1608-0603]  (hidden comment: 560112116006)
R57  value 4k7  [CR1608-0603]  (hidden comment: 560112116006)
R58  value 4k7  [CR1608-0603]  (hidden comment: 560112116006)
R59  value 4k7  [CR1608-0603]  (hidden comment: 560112116006)
R60  value 4k7  [CR1608-0603]  (hidden comment: 560112116006)
R61  value 10k  PackageReference: 0603  [CR1608-0603]  (hidden comment: 560112116005)
R62  value 4k7  PackageReference: 0603  [CR1608-0603]  (hidden comment: 560112116006)
R63  value 10k  PackageReference: 0603  [CR1608-0603]  (hidden comment: 560112116005)
R64  value 49R9  [CR1608-0603]  (hidden comment: 560112116133)
R65  value 5k1  [CR1608-0603]  (hidden comment: RC0603FR-075K1L)
R66  value 10k  [CR1608-0603]  (hidden comment: 560112116005)
R67  value 10k  [CR1608-0603]  (hidden comment: 560112116005)
R68  value 5k1  [CR1608-0603]  (hidden comment: RC0603FR-075K1L)
R69  value 49R9  [CR1608-0603]  (hidden comment: 560112116133)
R70  value 1k5  PackageReference: 0603  [CR1608-0603]  (hidden comment: 560112116038)
R71  value 1k5  PackageReference: 0603  [CR1608-0603]  (hidden comment: 560112116038)
S1  418121270808  [418121270808]
TP3  (no value)  [TESTPOINT 1.5mm]
TP4  (no value)  [TESTPOINT 1.5mm]
X6  value Male Header 1x3  PackageReference: Pitch 2.54mm  [HDR1X3]  (hidden comment: 61300311121)
Y2  value 25MHz  [CRYSTAL_3225]  (hidden comment: 830055299)

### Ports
D_N (bidir), D_P (bidir), MDC (in), MDIO (in), RX_CLK (out), RX_DV (out), RX_ER (out), RXD_0 (out), RXD_1 (out), RXD_2 (out), RXD_3 (out), TX_CLK (in), TX_EN (in), TX_ER (in), TXD_0 (in), TXD_1 (in), TXD_2 (in), TXD_3 (in), ~{INT} (in), ~{RESET} (in)

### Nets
+3V3: C61.1 C62.1 D23.2 D24.2 FB1.1 IC9.35(VDDIO) R60.2 R61.2 R70.1 R71.1 S1.9(A9) S1.10(A10) S1.11(A11) S1.12(A12) S1.13(A13) S1.14(A14) S1.15(A15) S1.16(A16)
GND: C55.1 C56.1 C57.2 C58.2 C59.2 C60.2 C61.2 C62.2 C63.2 C64.2 C65.2 D6.1(A) D7.1(A) D8.1(A) IC9.41(EP) Y2.2 Y2.4
CLK25_REF: IC9.7(CLK25_REF) TP3.1
D_N: R64.1 R65.1 ; port D_N
D_P: R68.1 R69.1 ; port D_P
~{INT}: D7.2(K) IC9.25(~{INT}) R70.2 X6.3 ; port ~{INT}
LINK_ST: IC9.4(LINK_ST/PHYAD_2) R60.1 TP4.1
MDC: D6.2(K) IC9.27(MDC) X6.1 ; port MDC
MDIO: D8.2(K) IC9.26(MDIO) R71.2 X6.2 ; port MDIO
~{RESET}: IC9.5(~{RESET}) ; port ~{RESET}
RX_CLK: IC9.32(EX_CLK/RXC/MACIF_SEL0) R55.1 ; port RX_CLK  [project net P0_INCLK]
RX_DV: IC9.33(RX_DV/RX_CTL/~{SWPD_EN}) R54.1 ; port RX_DV  [project net P0_INDV]
RX_ER: IC9.34(RX_ER/MACIF_SEL1) R53.1 ; port RX_ER  [project net P0_INER]
RXD_0: IC9.31(RXD_0/~{TX2P4_EN}) R56.1 ; port RXD_0  [project net P0_IND0]
RXD_1: IC9.30(RXD_1/MS_SEL) R57.1 ; port RXD_1  [project net P0_IND1]
RXD_2: IC9.29(RXD_2/PHYAD_0) R58.1 ; port RXD_2  [project net P0_IND2]
RXD_3: IC9.28(RXD3/PHYAD_1) R59.1 ; port RXD_3  [project net P0_IND3]
TX_CLK: IC9.38(TX_CLK/TXC) ; port TX_CLK  [project net P0_OUT/REF_CLK_MODE0]
TX_EN: IC9.37(TX_EN/TX_CTL) ; port TX_EN  [project net P0_OUTDV]
TX_ER: IC9.36(TX_ER) ; port TX_ER  [project net P0_OUTER_SPEED]
TXD_0: IC9.39(TXD_0) ; port TXD_0  [project net P0_OUTD0_MODE1]
TXD_1: IC9.40(TXD_1) ; port TXD_1  [project net P0_OUTD1_MODE2]
TXD_2: IC9.1(TXD_2) ; port TXD_2  [project net P0_OUTD2_MODE3]
TXD_3: IC9.2(TXD_3/MEDIA_CNV) R52.1 ; port TXD_3  [project net P0_OUTD3]
NetC55_2: C55.2 IC9.8(XTAL_I/CLK_IN) Y2.1
NetC56_2: C56.2 IC9.9(XTAL_O) Y2.3
NetC57_1: C57.1 C58.1 C63.1 C64.1 FB1.2 IC9.16(AVDD_H) IC9.17(AVDD_H) IC9.22(AVDD_L)
NetC59_1: C59.1 IC9.19(CEXT_2)
NetC60_1: C60.1 IC9.20(CEXT_3)
NetC65_1: C65.1 IC9.23(DLDO_1P1) IC9.24(DVDD_1P1)
NetD23_1: D23.1 R62.1
NetD24_1: D24.1 R63.2
NetIC9_3: IC9.3(LED_0) R63.1
NetIC9_6: IC9.6(LED_1) R61.1 R62.2
NetIC9_12: IC9.12(TXN) R64.2 R66.1
NetIC9_13: IC9.13(RXN) R65.2 R67.1
NetIC9_14: IC9.14(RXP) R66.2 R68.2
NetIC9_15: IC9.15(TXP) R67.2 R69.2
NetR52_2: R52.2 S1.1(A1)
NetR53_2: R53.2 S1.2(A2)
NetR54_2: R54.2 S1.3(A3)
NetR55_2: R55.2 S1.4(A4)
NetR56_2: R56.2 S1.5(A5)
NetR57_2: R57.2 S1.6(A6)
NetR58_2: R58.2 S1.7(A7)
NetR59_2: R59.2 S1.8(A8)

Not connected (* = marked no-connect by the designer): IC9 10(DNC)* 11(DNC)* 18(DNC)* 21(DNC)*

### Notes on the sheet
- ADIN1100 HARDWARE CONFIGURATION
- MEDIA_CNV
- MACIF_SEL1
- SWPD_N
- MACIF_SEL0
- TX2P4_DIS
- MS_SEL
- PHYAD_0
- PHYAD_1
- PHYAD_2
- (*PHYAD_2 default=0 here)
- MDIO
  management
  interface
- Rev.
- Content
- Date
- Name
- WÜRTH Elektronik eiSos
- Customer:
- Print Date :
- Size
- A3
- Document Number
- Design Date :
- Modified By:
- Sheet:
- of
- Rev

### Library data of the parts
C55 C56 = 885012005056: as C53 on sheet 01-PSE_Power_MCU
C57 C59 C62 C63 = 885012206071: as C44 on sheet 01-PSE_Power_MCU
C58 C61 C64 = 885012206040: as C45 on sheet 01-PSE_Power_MCU
C60 = 885012206052: as C52 on sheet 01-PSE_Power_MCU
C65 = 885012206051: CAP, CERM, 680nF, 16V, +/-10%, X7R, 0603; Manufacturer: Wurth; Polarized: N; TaMax_C: 125; TaMin_C: -55; Tolerance_%: 10; CompType: Capacitor
D6-D8 = 824500500: DIODE, TVS , 5V, 400W, Unidirection, SMA; Manufacturer: Wurth
D23 = LTST-C190KSKT: LED 587NM YELLOW 0603 SMD; Manufacturer: Lite-On Inc.
D24 = 150060VS75020: LED 572NM GREEN 0603 SMD; Manufacturer: Wurth
FB1 = 742792031: as FB10 on sheet 01-PSE_Power_MCU
IC9 = ADIN1100CCPZ-R7: IC Ethernet 10BASE-T1L PHY, 3.3V, LFCSP-40; Manufacturer: Microchip
R52-R60 R62 = 560112116006: as R39 on sheet 01-PSE_Power_MCU
R61 R63 R66 R67 = 560112116005: as R30 on sheet 01-PSE_Power_MCU
R64 R69 = 560112116133: RES, 49.9 ohm, 1%, 0.1W, 0603; Manufacturer: Wurth; CompType: Resistor; Power_W: 0.1
R65 R68 = RC0603FR-075K1L: as R3 on sheet 01-PSE_Power_MCU
R70 R71 = 560112116038: RES, 1.5kohm, 1%, 0.1W, 0603; Manufacturer: Wurth; CompType: Resistor; Power_W: 0.1
S1 = 418121270808: DIP SWITCH, SPST, 0.025A, 24V; Manufacturer: Wurth
TP3 TP4 = TP / 1.5mm: Test Point, SMT, Miniature; Value: 1.5mm
X6 = 61300311121: as X9 on sheet 01-PSE_Power_MCU
Y2 = 830055299: Crystal / 25MHz / 18pF / 30ppm; Manufacturer: Wurth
